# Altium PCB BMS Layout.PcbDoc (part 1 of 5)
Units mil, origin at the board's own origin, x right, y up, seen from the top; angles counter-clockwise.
Board outline 5576.78 x 4051.82 mil, 6 copper layers (Top Layer, GND1, Analog Signal, Power, GND2, Bottom Layer), stack 61.2 mil thick; 425 components, 206 nets, 1164 pads, 390 vias.
Unrouted connection lines stored in the file: 32.
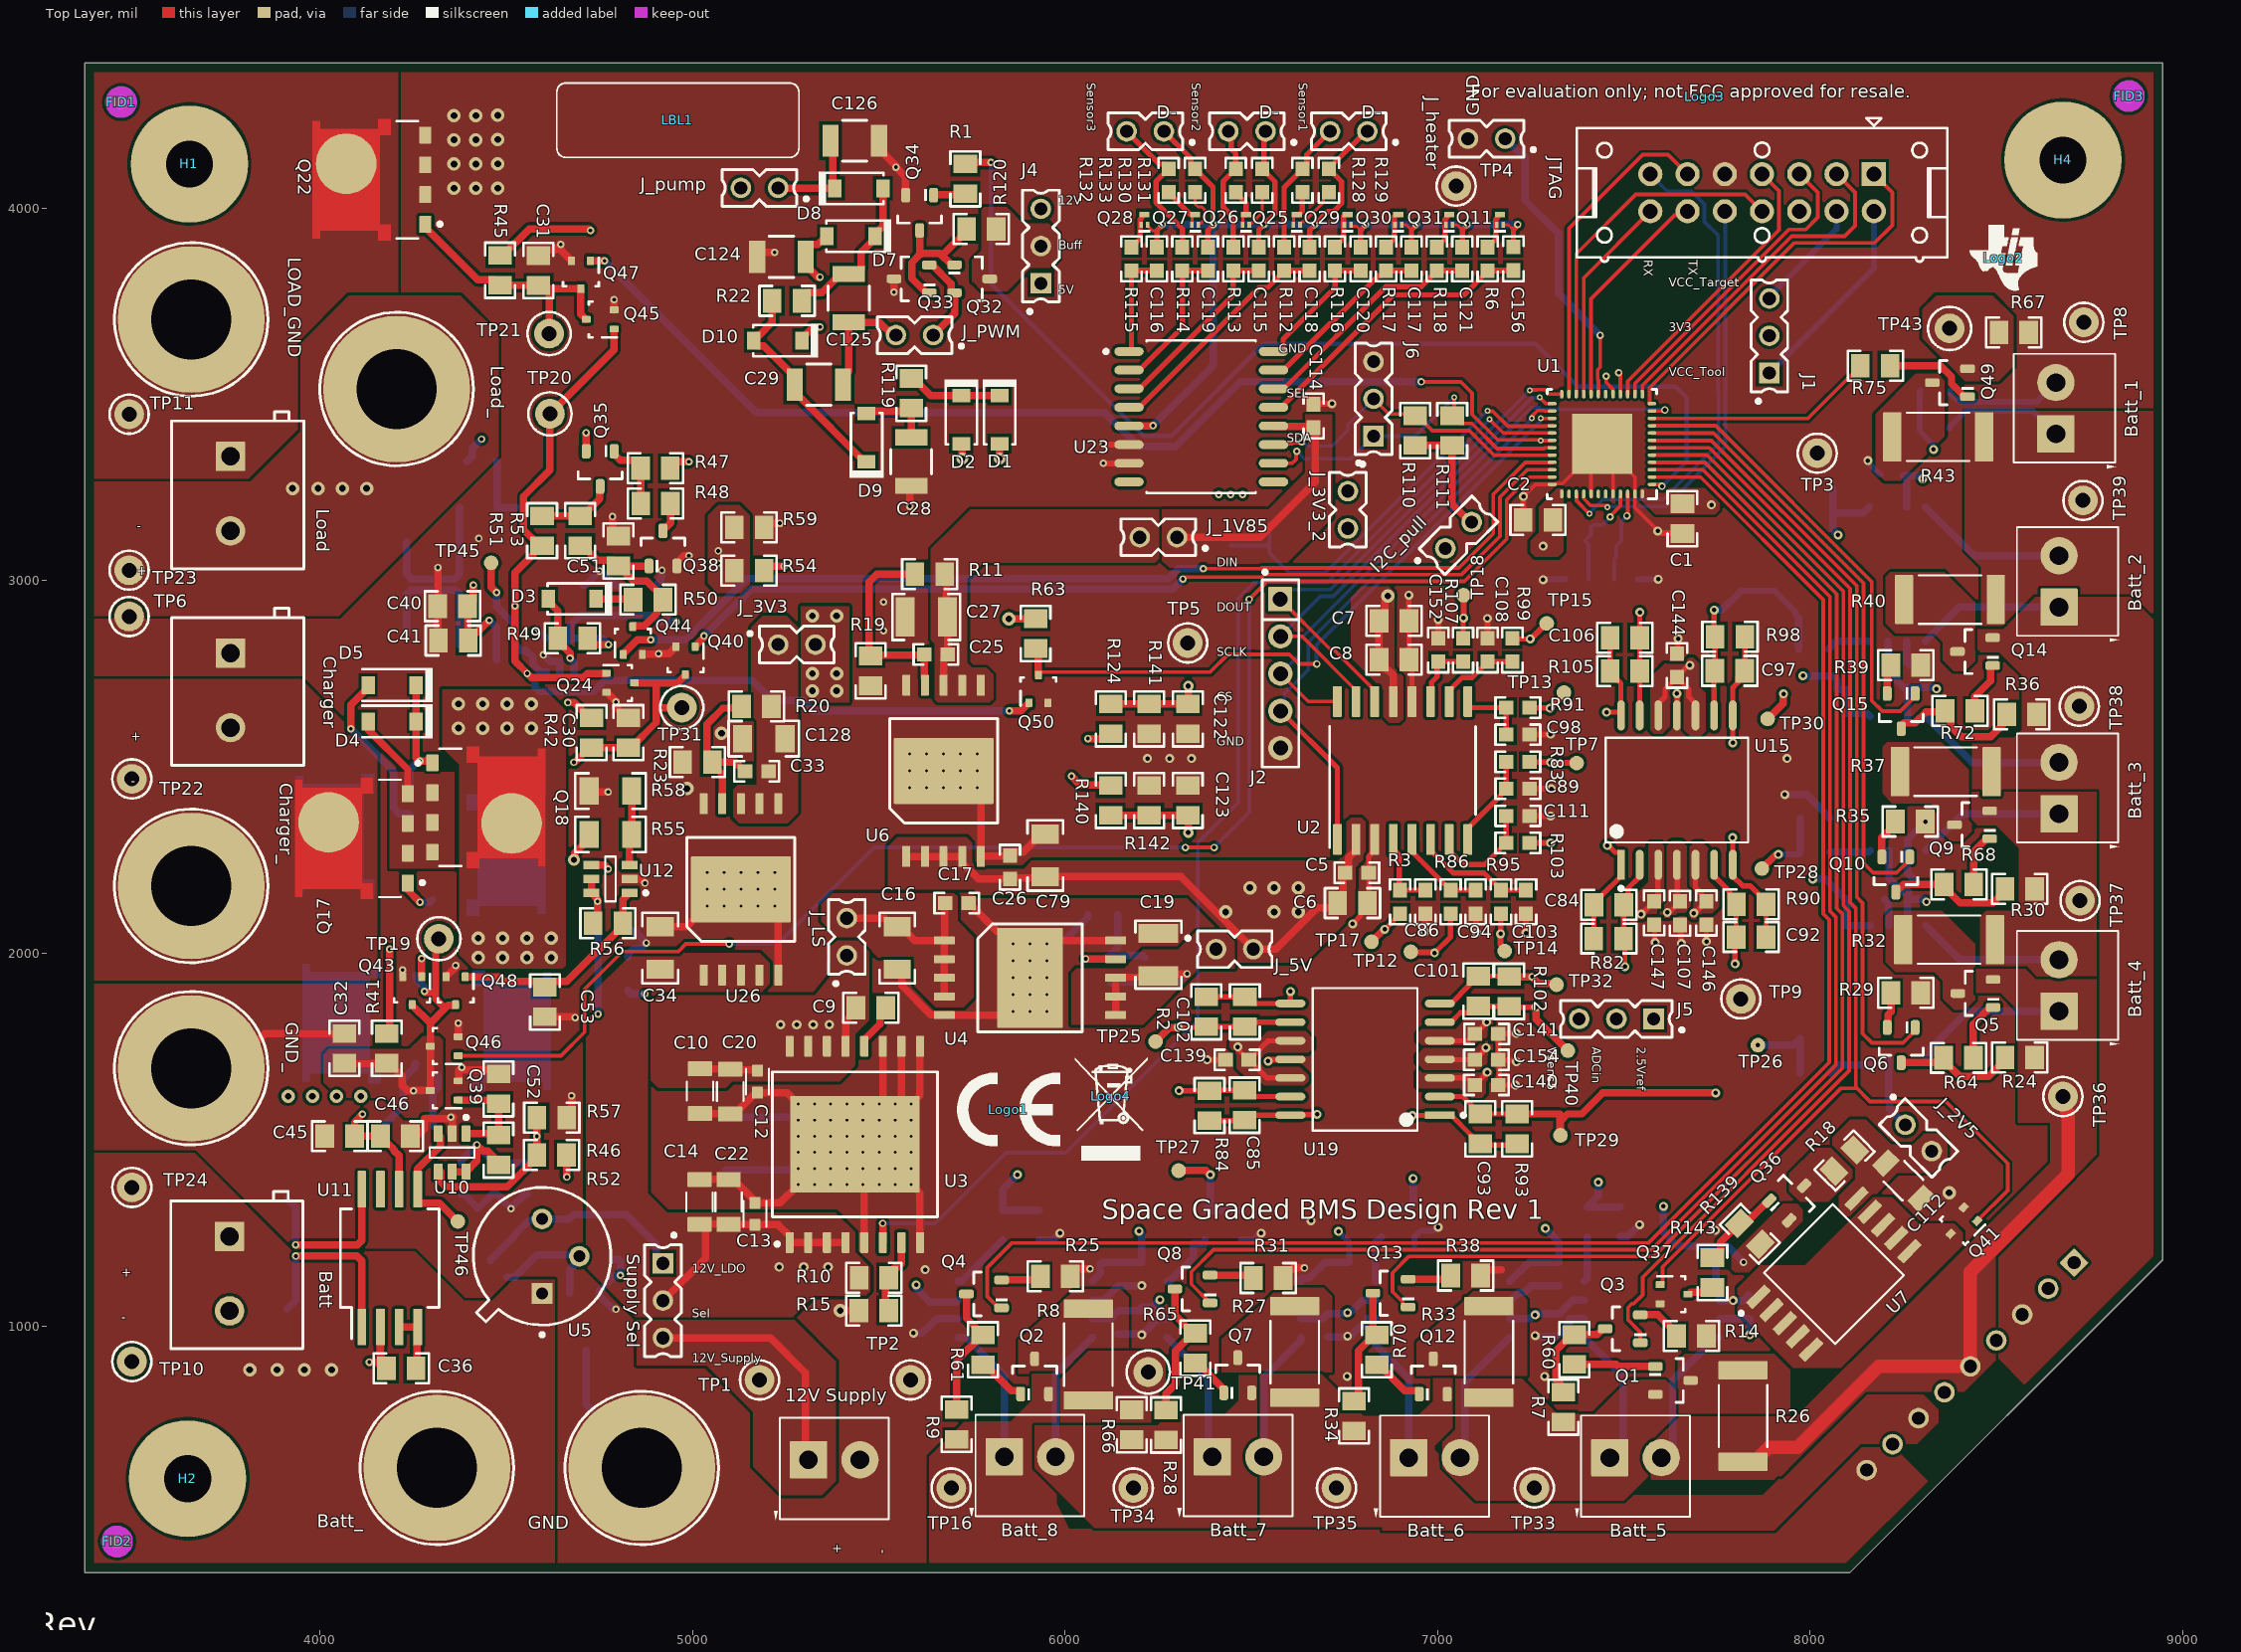
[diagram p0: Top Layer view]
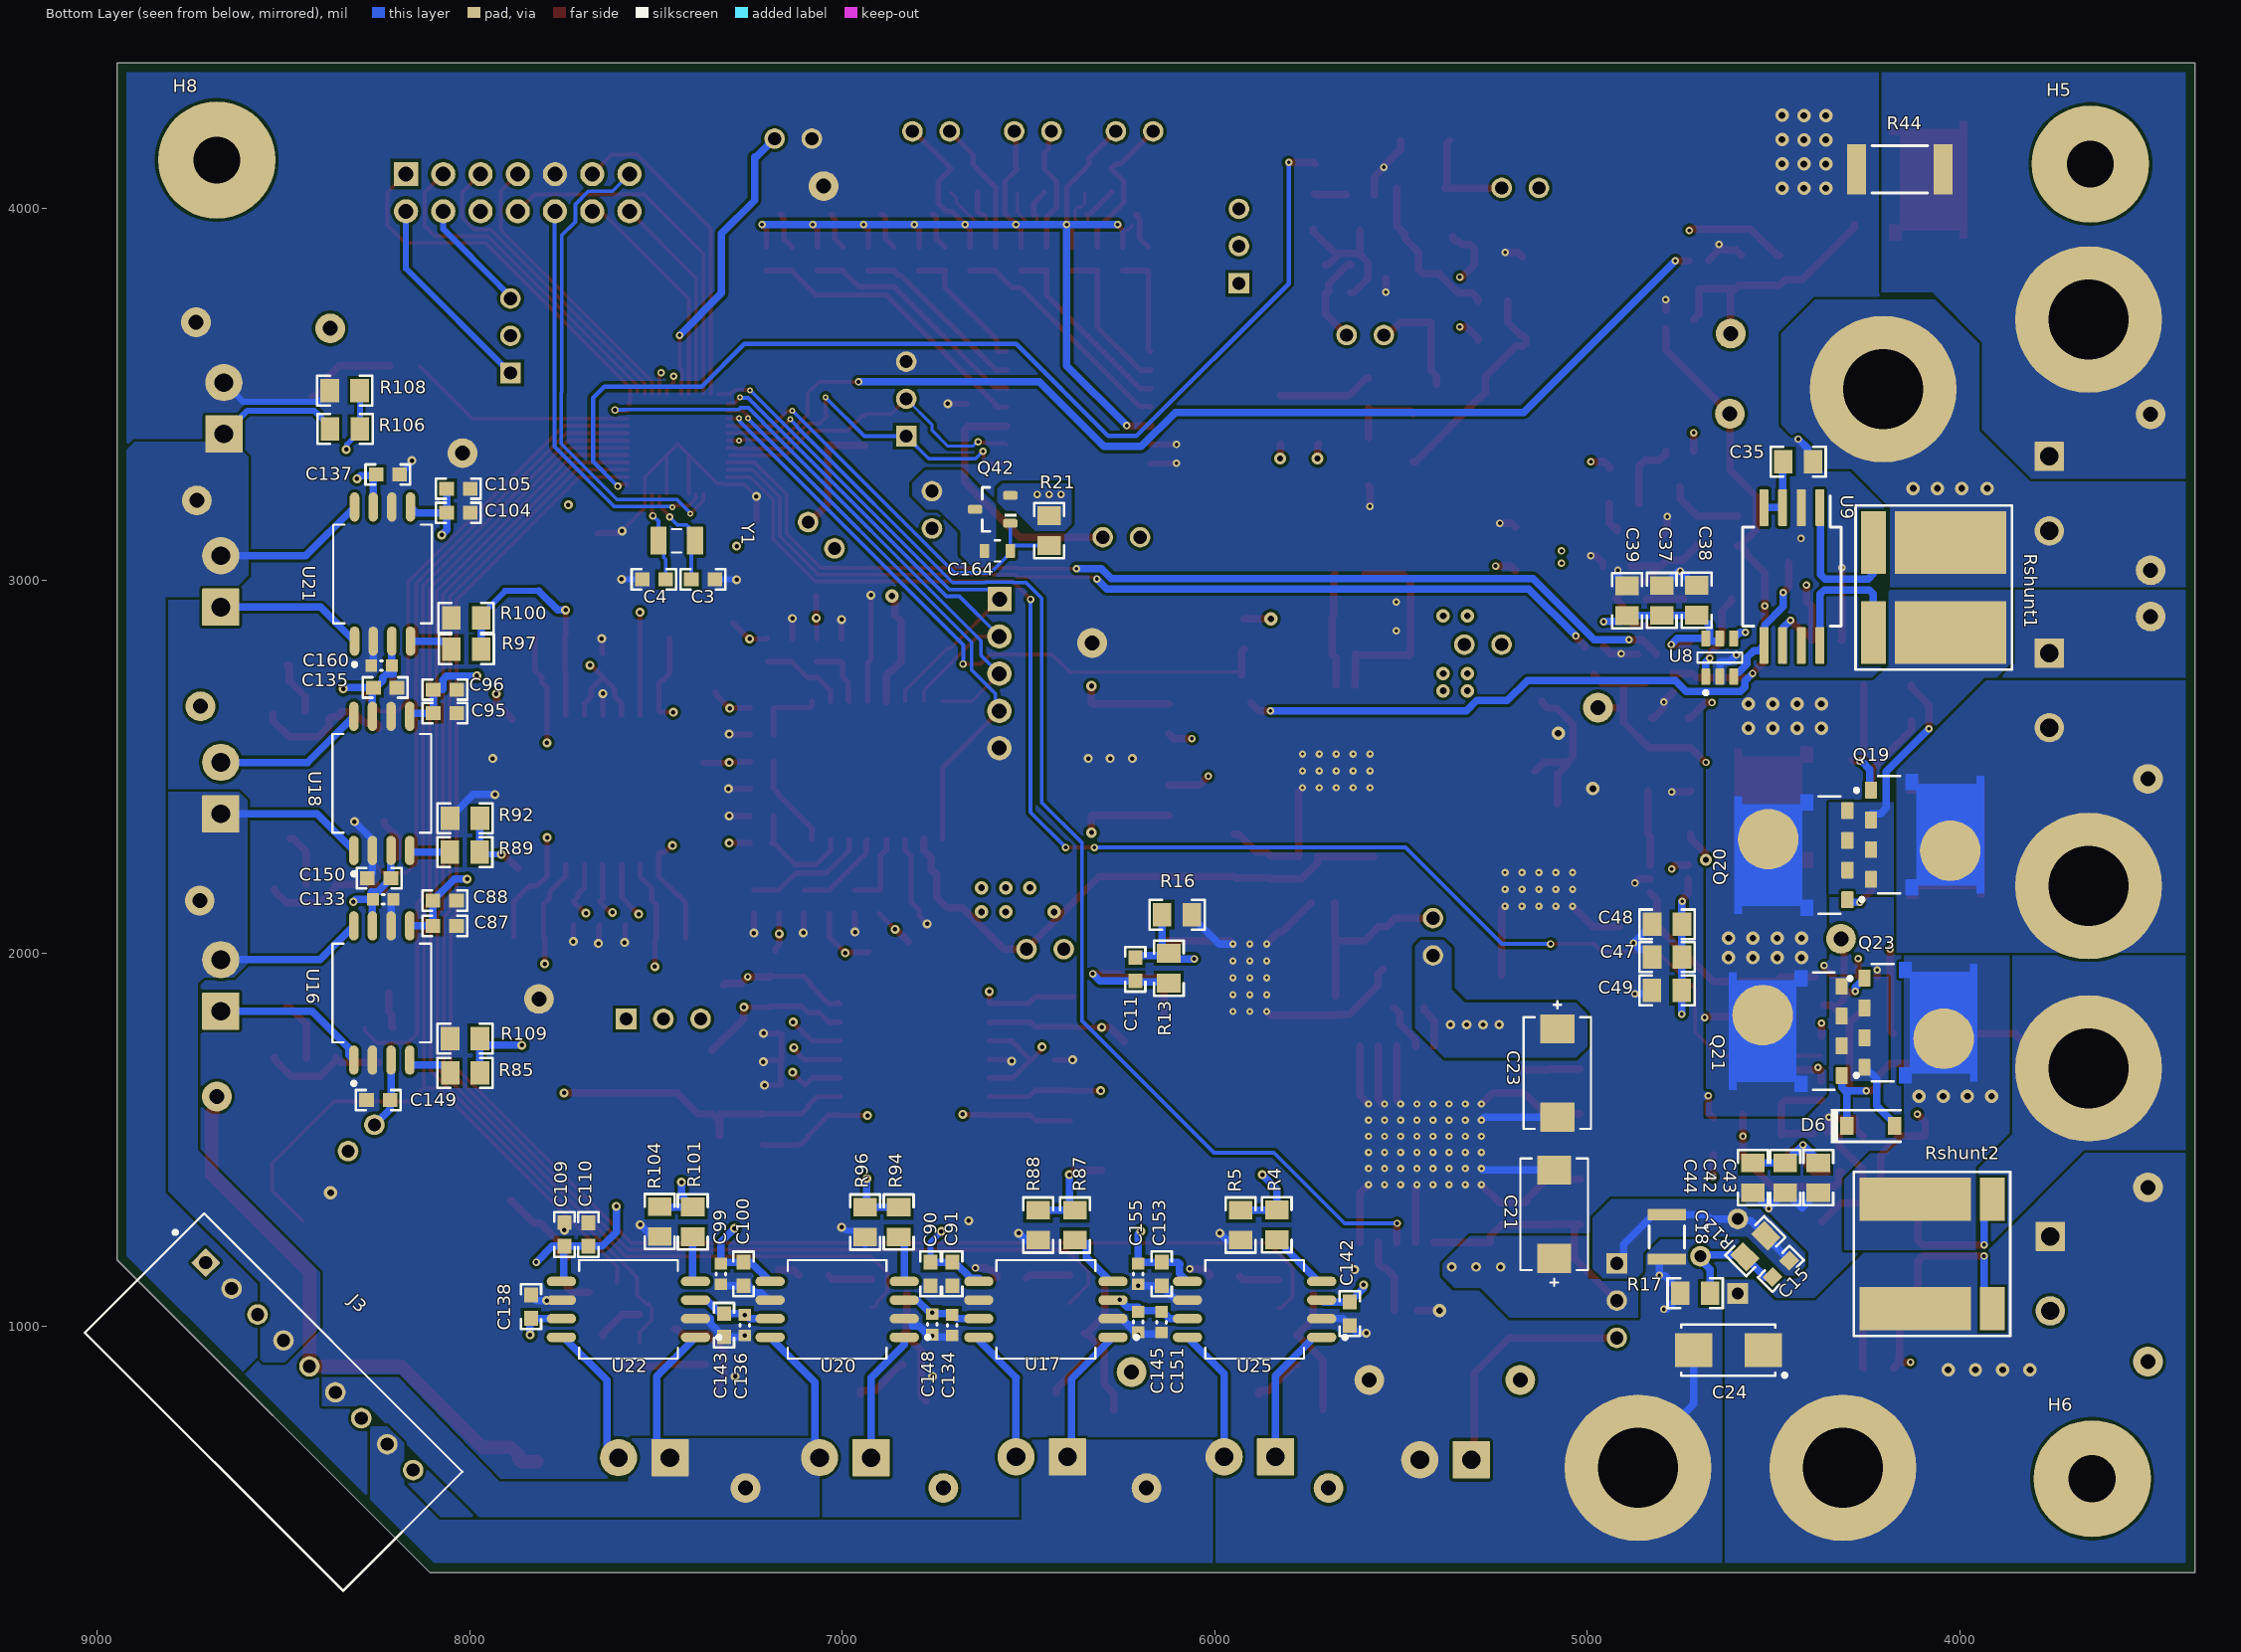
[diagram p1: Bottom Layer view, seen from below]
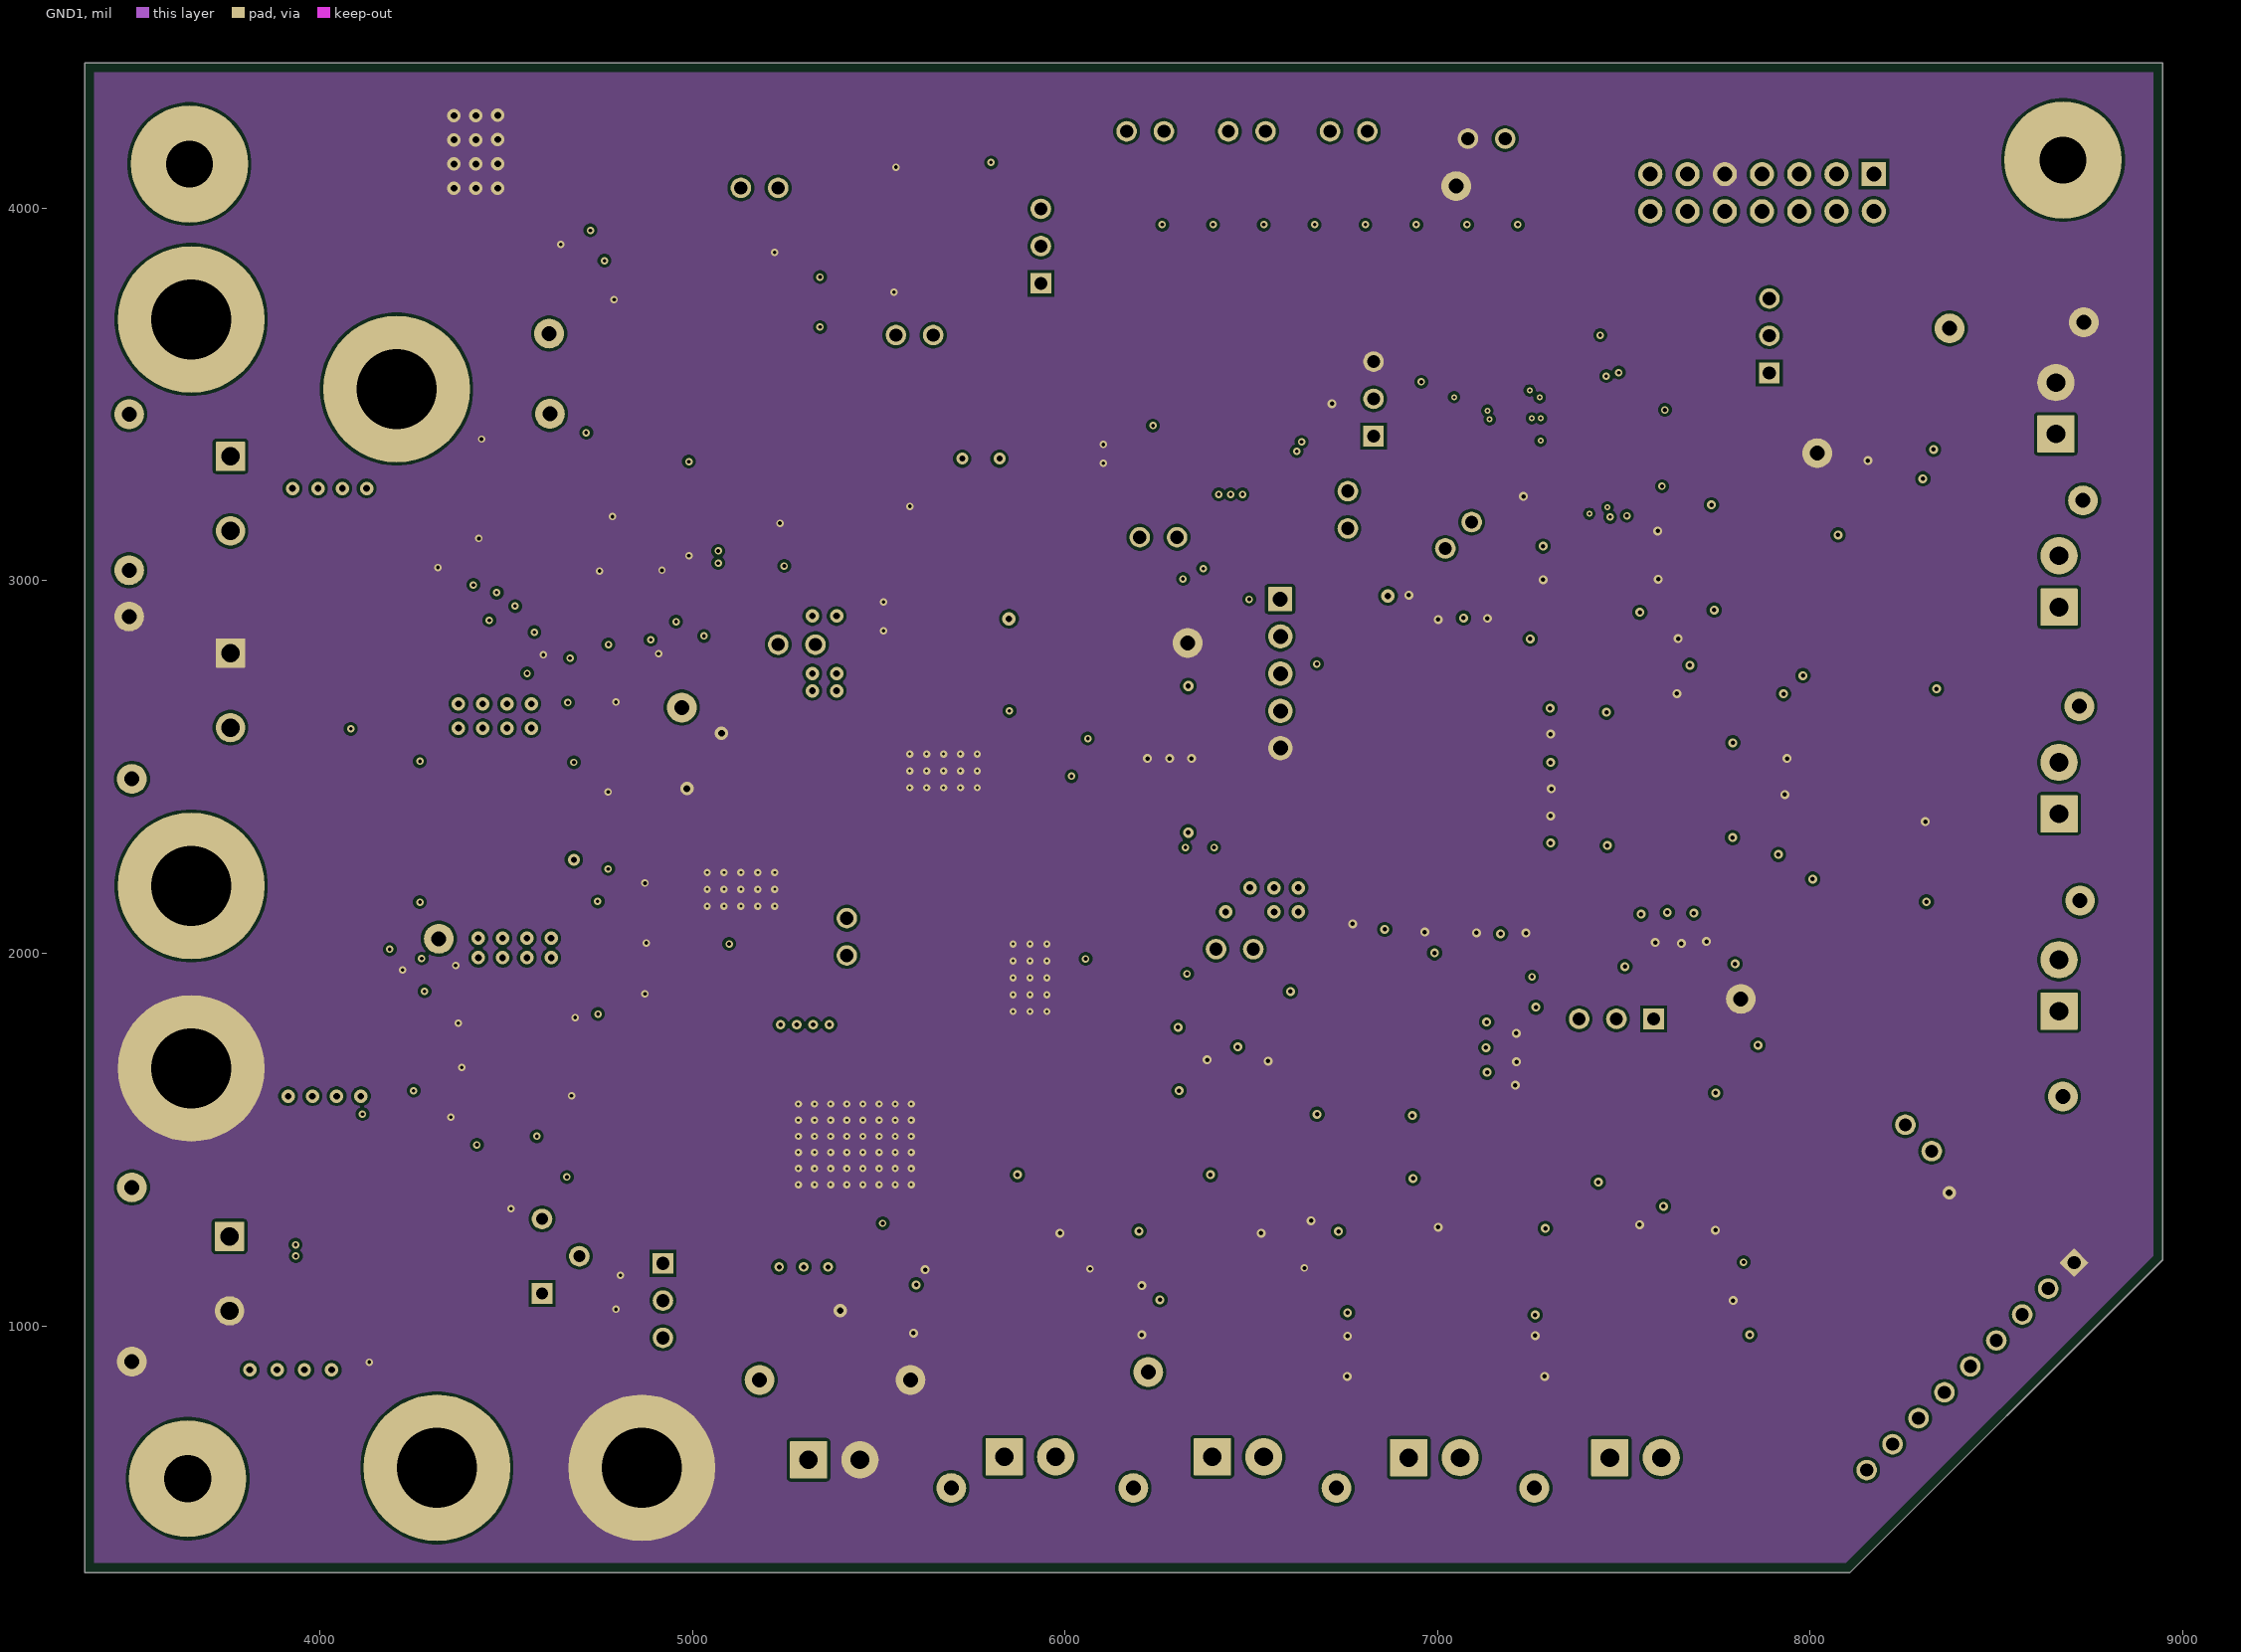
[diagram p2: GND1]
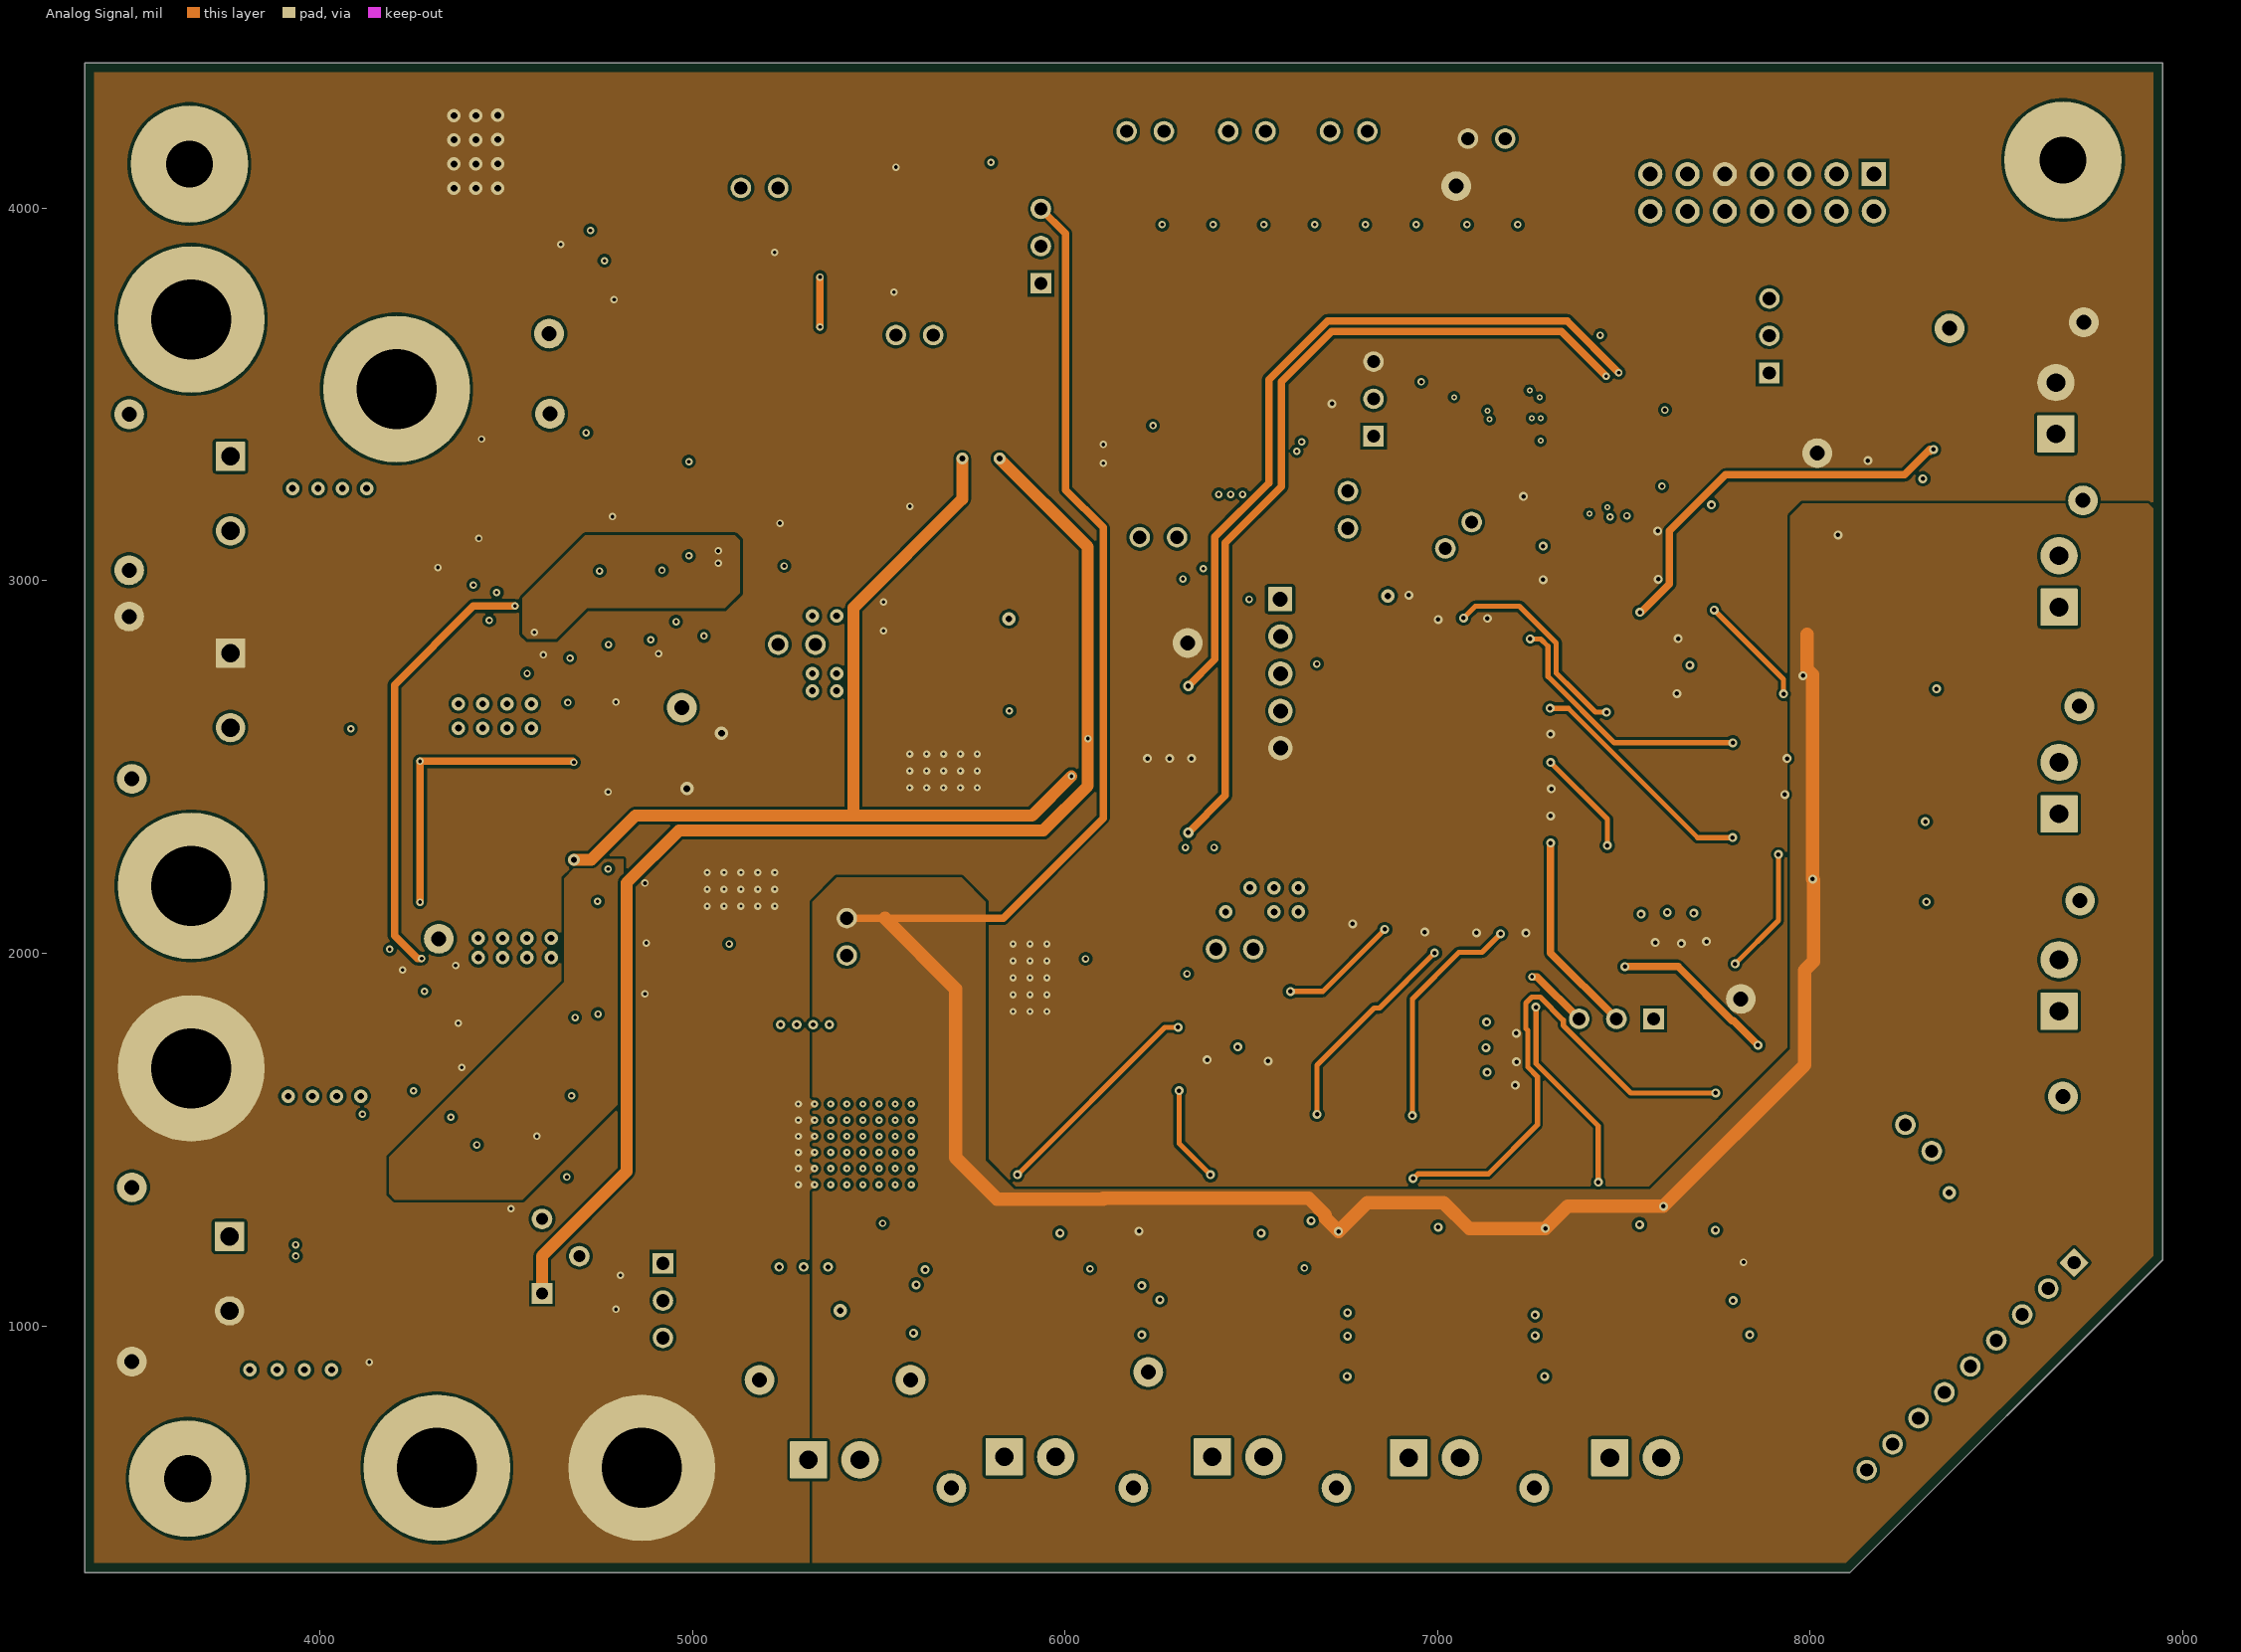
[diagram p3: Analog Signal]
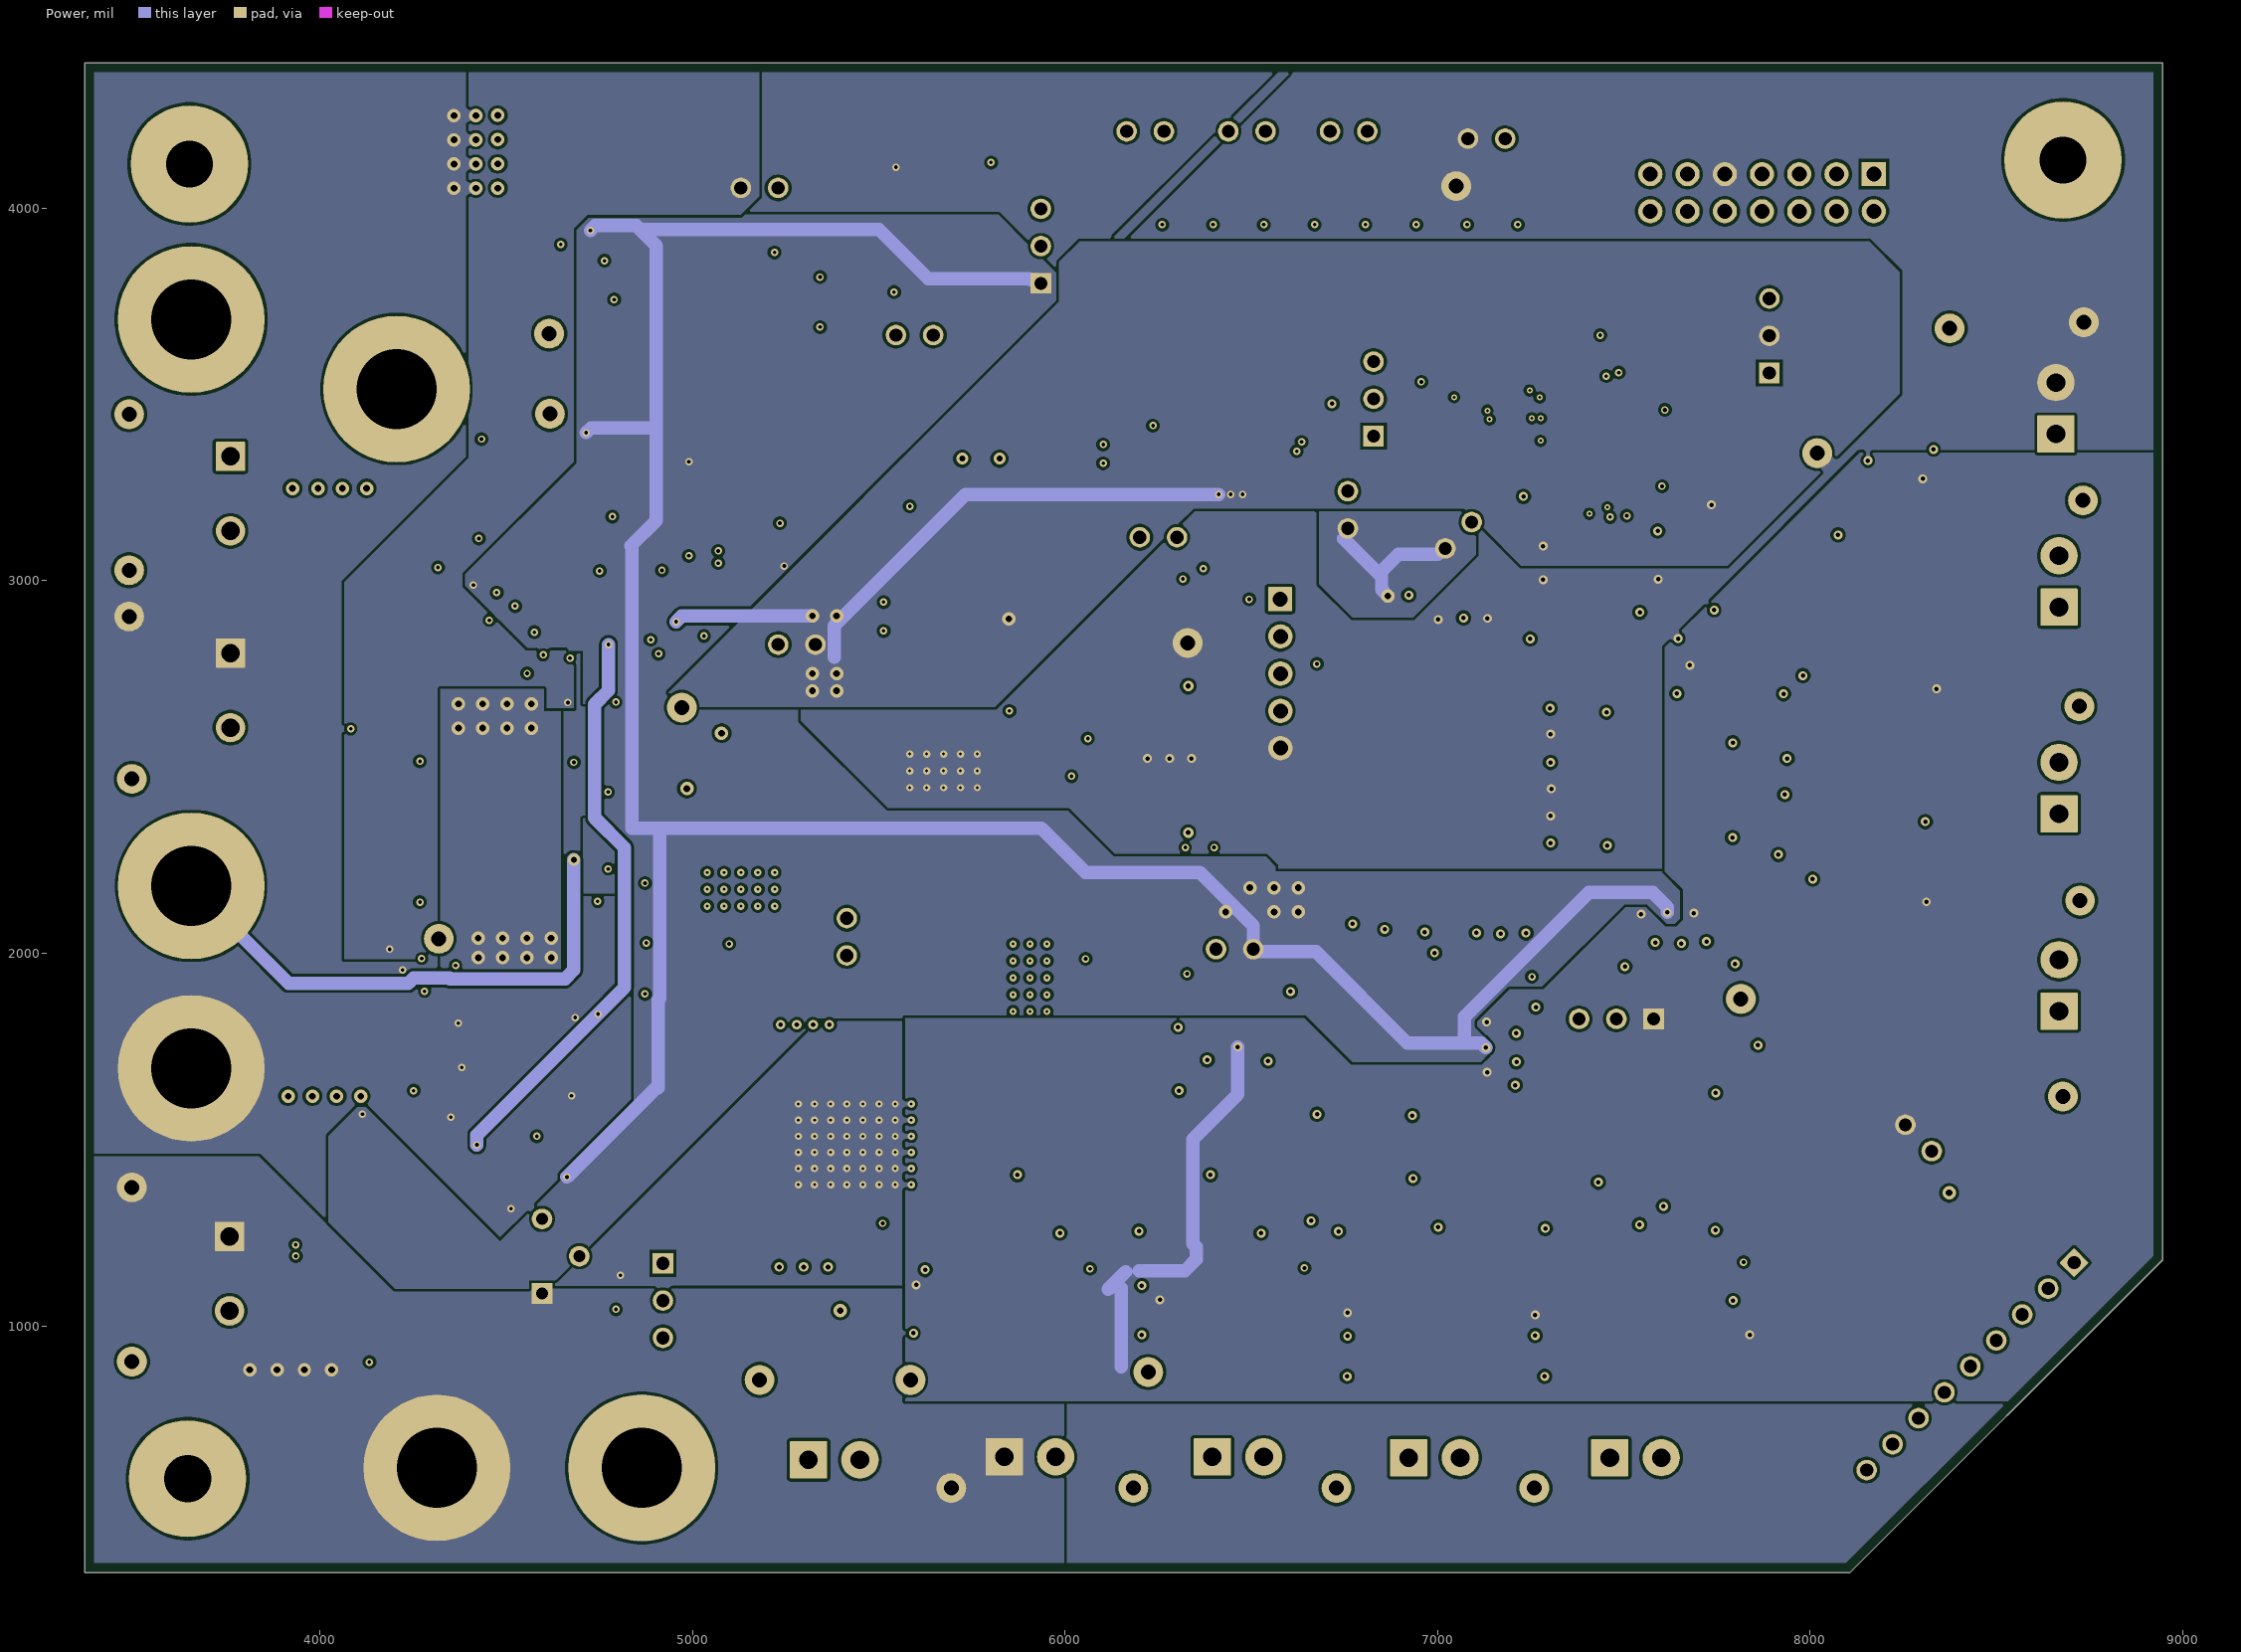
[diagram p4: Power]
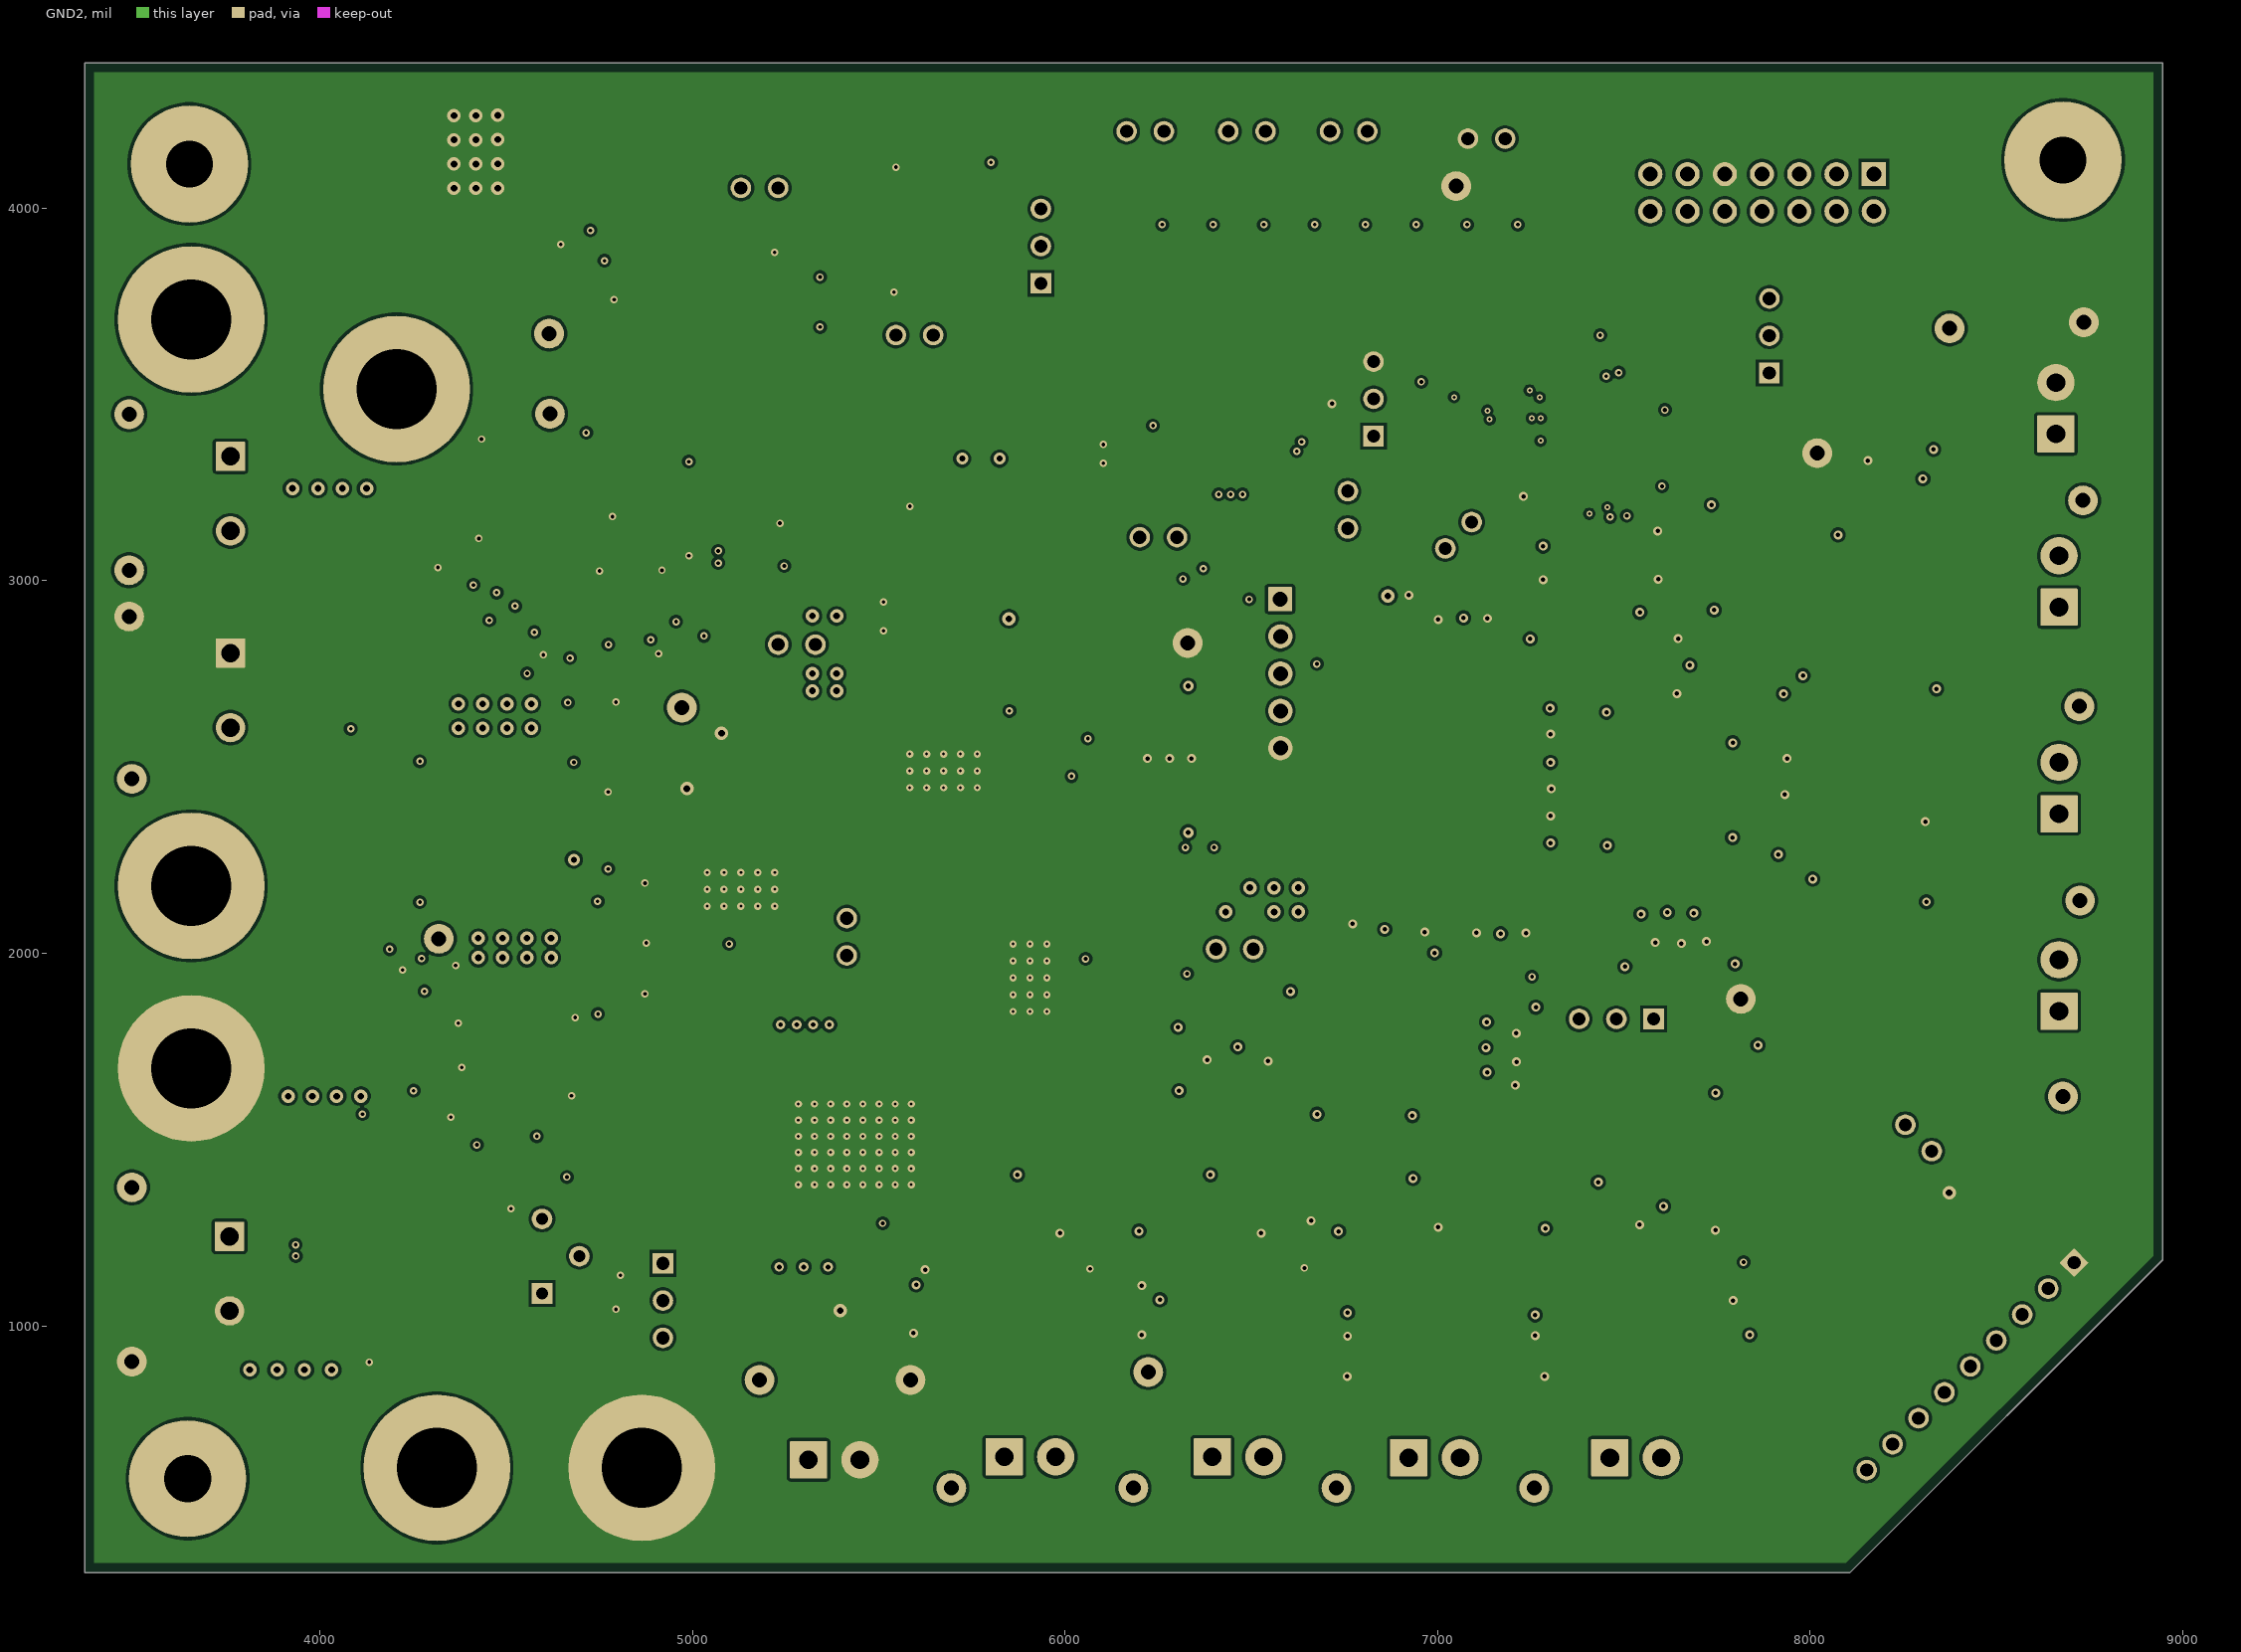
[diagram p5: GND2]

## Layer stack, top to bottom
Top Solder: solder mask 0.4, Solder Resist, Dk 3.5
Top Layer: signal copper 2.756
Dielectric 1: prepreg 2.8, PP-006, Dk 4.1
GND1: signal copper 1.378
Dielectric 3: prepreg 2.8, PP-006, Dk 4.1
Analog Signal: signal copper 1.378
Dielectric1: core 38.976, FR-4 High Tg, Dk 4.8
Power: signal copper 1.378
Dielectric 4: prepreg 2.8, PP-006, Dk 4.1
GND2: signal copper 1.378
Dielectric 2: prepreg 2.8, PP-006, Dk 4.1
Bottom Layer: signal copper 2.756
Bottom Solder: solder mask 0.4, Solder Resist, Dk 3.5

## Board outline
3369.09,337.94 3369.09,4389.76 8945.87,4389.76 8945.87,1177.18 8106.64,337.94

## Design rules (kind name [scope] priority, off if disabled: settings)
AcuteAngle [All] p1: minimum=4.50000000000000E+0001 checktracksonly=FALSE
AssemblyTestPointUsage [All] p1: valid=2
BoardOutlineClearance BoardOutlineClearance_MountingHoles [OnCopper and InComponentClass('Mounting Holes')] p1: gap=39.37 ignorepadtopadclearanceinfootprint=FALSE
BoardOutlineClearance BoardOutlineClearance_Poly [OnCopper and IsPoly] p2: gap=25 ignorepadtopadclearanceinfootprint=FALSE
BoardOutlineClearance [OnCopper and Not InComponentClass('Logo') and not InComponentClass('FiducialMark') and not InRegion(1000,500,4000,800) and not InPoly] p3: gap=75 ignorepadtopadclearanceinfootprint=FALSE except(40: Via-OutlineEdge; 50: Track-OutlineEdge Track-CavityEdge Track-CutoutEdge Track-SplitBarrior Track-SplitContinuation)
Clearance Clearance_FiducialMark [IsKeepOut and InComponentClass('FiducialMark') vs IsPad and InComponentClass('FiducialMark')] p1: gap=0 ignorepadtopadclearanceinfootprint=FALSE
Clearance [All] p2: gap=8 ignorepadtopadclearanceinfootprint=TRUE except(6: SMDPad-Via)
Clearance Clearance_Keepouts [((IsTrack Or IsArc) And Not InPoly) And IsFree and IsKeepOut vs ((IsTrack Or IsArc) And Not InPoly) And IsFree and IsKeepOut] p3: gap=0 ignorepadtopadclearanceinfootprint=FALSE
Clearance Clearance_Poly [InPolygon] p4: gap=15 ignorepadtopadclearanceinfootprint=FALSE
ComponentClearance ComponentClearance_MountingHoles_FiducialMarks [InComponentClass('Mounting Holes') vs InComponentClass('FiducialMark')] p1: gap=50 collisioncheckmode=3 verticalgap=10 showdistances=FALSE
ComponentClearance ComponentClearance_Shunt [InComponentClass('Header') vs InComponentClass('Shunt')] p2: gap=0 collisioncheckmode=3 verticalgap=0 showdistances=FALSE
ComponentClearance ComponentClearance_Logo [InComponentClass('Logo')] p3: gap=50 collisioncheckmode=3 verticalgap=10 showdistances=FALSE
ComponentClearance ComponentClearance_ScrewToNut [(HasFootprint('NY PMS 440 0025 PH')) vs (HasFootprint('Keystone_1902C'))] p4: gap=5 collisioncheckmode=3 verticalgap=10 showdistances=FALSE
ComponentClearance ComponentClearance_MountingHoles [InComponentClass('Mounting Holes')] p5: gap=39.37 collisioncheckmode=3 verticalgap=100000 showdistances=FALSE
ComponentClearance ComponentClearance_SmallPassives [HasFootprint('0201*') or HasFootprint('0402*') or HasFootprint('0508') or HasFootprint('0603*') or HasFootprint('0612') or HasFootprint('0805*') or HasFootprint('0815*') or HasFootprint('0830*') or HasFootprint('1206*') or HasFootprint('1210*') or HasFootprint('1808*') or HasFootprint('1812*') or HasFootprint('1825*') or HasFootprint('2010*') or HasFootprint('2220*') or HasFootprint('2225*') or HasFootprint('2512*') or HasFootprint('2728*') or HasFootprint('3518*') vs HasFootprint('0201*') or HasFootprint('0402*') or HasFootprint('0508') or HasFootprint('0603*') or HasFootprint('0612') or HasFootprint('0805*') or HasFootprint('0815*') or HasFootprint('0830*') or HasFootprint('1206*') or HasFootprint('1210*') or HasFootprint('1808*') or HasFootprint('1812*') or HasFootprint('1825*') or HasFootprint('2010*') or HasFootprint('2220*') or HasFootprint('2225*') or HasFootprint('2512*') or HasFootprint('2728*') or HasFootprint('3518*')] p6: gap=14.96 collisioncheckmode=3 verticalgap=10 showdistances=FALSE
ComponentClearance ComponentClearance_THtoSMT [IsThruComponent vs IsSMTComponent] p7: gap=9.84 collisioncheckmode=3 verticalgap=30 showdistances=FALSE
ComponentClearance ComponentClearance_THtoTH [IsThruComponent vs IsThruComponent] p8: gap=9.84 collisioncheckmode=3 verticalgap=30 showdistances=FALSE
ComponentClearance [All] p9: gap=9.84 collisioncheckmode=3 verticalgap=10 showdistances=FALSE
DiffPairsRouting [All] p1: maxlimit=100 minlimit=10 mostfreqgap=10 toplayer_minwidth=15 toplayer_maxwidth=15 toplayer_prefwidth=15 midlayer1_minwidth=15 midlayer1_maxwidth=15 midlayer1_prefwidth=15 midlayer2_minwidth=15 midlayer2_maxwidth=15 midlayer2_prefwidth=15 midlayer3_minwidth=15 midlayer3_maxwidth=15 midlayer3_prefwidth=15 midlayer4_minwidth=15 midlayer4_maxwidth=15 midlayer4_prefwidth=15 bottomlayer_minwidth=15 bottomlayer_maxwidth=15 bottomlayer_prefwidth=15 maxuncoupledlength=1000
FabricationTestPointUsage TestPointUsage [All] p1: valid=2 allowmultiple=FALSE
FabricationTestpoint Testpoint [All] p1: side=3 testpointundercomponent=TRUE minsize=40 maxsize=100 preferedsize=60 minholesize=0 maxholesize=40 preferedholesize=32 testpointgrid=1 allowsidetop=TRUE allowsidebottom=TRUE usegrid=TRUE gridtolerance=0.01
FanoutControl Fanout_LCC [IsLCC] p1: bgadir=Out bgaviamode=Centered fanoutstyle=Auto fanoutdirection=Alternating viagrid=1 // Fanout_LCC (Default Rule)
FanoutControl Fanout_BGA [IsBGA] p2: bgadir=Out bgaviamode=Centered fanoutstyle=Auto fanoutdirection=Alternating viagrid=1 // Fanout_BGA (Default Rule)
FanoutControl Fanout_Default [All] p4: bgadir=Out bgaviamode=Centered fanoutstyle=Auto fanoutdirection=Alternating viagrid=1 // Fanout_Default (Default Rule)
FanoutControl Fanout_Small [(CompPinCount < 5)] p5: bgadir=Out bgaviamode=Centered fanoutstyle=Auto fanoutdirection=OutThenIn viagrid=1 // Fanout_Small (Default Rule)
HoleSize [All] p1: absolutevalues=TRUE maxlimit=251 minlimit=7.87 maxpercent=80.000 minpercent=20.000
MinimumAnnularRing MinimumAnnularRing_ThermalPadVias [IsVia and InAnyComponent] p1: minimumring=5.91
MinimumAnnularRing [All] p2: minimumring=4
MinimumSolderMaskSliver MinimumSolderMaskSliver_Logo [InComponentClass('Logo') vs InComponentClass('Logo')] p1: minsoldermaskwidth=0.7
MinimumSolderMaskSliver [All] p2: minsoldermaskwidth=3
NetAntennae [All] p1 off: netantennaetolerance=0
PlaneConnect [All] p1: planeconnectstyle=Direct reliefexpansion=10 reliefentries=4 reliefconductorwidth=10 reliefairgap=10
PolygonConnect [All] p1: connectstyle=Direct reliefconductorwidth=10 reliefentries=4 polygonreliefangle="90 Angle" airgapwidth=10
RoutingVias ThermalPadVias [IsVia and InAnyComponent] p1: holewidth=7.87 width=19.68 viastyle="Through Hole" minholewidth=6 minwidth=16 maxholewidth=12.99 maxwidth=23.62
RoutingVias [All] p2: holewidth=10 width=20 viastyle="Through Hole" minholewidth=8 minwidth=16 maxholewidth=40 maxwidth=65
SilkToBoardRegionClearance [Not ((IsComment or IsDesignator) And (Hide <> 'False')) and not InRegion(1000,500,4000,800)] p1:
SilkToSilkClearance SilkToSilkClearance_Pb-FreeLogo [(HasFootprint('Pb-Free_Overlay_Medium') OR HasFootprint('Pb-Free_Overlay_Small')) vs (HasFootprint('Pb-Free_Overlay_Medium') OR HasFootprint('Pb-Free_Overlay_Small'))] p1: silktosilkclearance=0
SilkToSilkClearance [All] p2: silktosilkclearance=1
SilkToSolderMaskClearance SilkToComponentPadClearance [(IsPad or IsFill or IsRegion) and InAnycomponent] p1: minsilkscreentomaskgap=0 clearancetoexposedcopper=TRUE
SilkToSolderMaskClearance "Silk to Solder Mask Opening" [All] p2: minsilkscreentomaskgap=3 clearancetoexposedcopper=FALSE
SolderMaskExpansion [All] p1: expansion=1.97 istentingtop=FALSE
UnRoutedNet [All] p1: checkbadconnections=TRUE
Width [All] p1: maxlimit=100 minlimit=6 preferedwidth=20 midlayer1_prefwidth=10 midlayer2_prefwidth=10 midlayer4_prefwidth=36 minimp=50.000000 maximp=50.000000 favimp=50.000000 checkconnectedcopper=TRUE
13 further rules are at their usual default settings.

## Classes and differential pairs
component class "Batt_Stack_Control (NMOS)": Batt Batt_ C28 C29 C30 C31 C32 C35 C36 C37 C38 C39 C40 C41 C42 C43 C44 C45 C46 C47 C48 C49 C51 C52 C53 C124 C125 C126 Charger Charger_ D1 D2 D3 D4 D5 D6 D7 D8 D9 D10 GND GND_ J4 J_pump J_PWM Load Load_ LOAD_GND Q17 Q18 Q19 Q20 Q21 Q22 Q23 Q24 Q32 Q33 Q34 Q35 Q38 Q39 Q40 Q43 Q44 Q45 Q46 Q47 Q48 Q50 Q100 R1 R22 R41 R42 R44 R45 R46 R47 R48 R49 R50 R51 R52 R53 R54 R55 R56 R57 R58 R59 R63 R119 R120 Rshunt1 Rshunt2 TP11 TP19 TP20 TP21 TP22 TP23 TP24 TP31 TP45 TP46 U8 U9 U10 U11 U12
component class Balancer: Batt_1 Batt_2 Batt_3 Batt_4 Batt_5 Batt_6 Batt_7 Batt_8 J3 Q1 Q2 Q3 Q4 Q5 Q6 Q7 Q8 Q9 Q10 Q12 Q13 Q14 Q15 Q49 R7 R8 R9 R14 R24 R25 R26 R27 R28 R29 R30 R31 R32 R33 R34 R35 R36 R37 R38 R39 R40 R43 R60 R61 R64 R65 R66 R67 R68 R70 R72 R75 TP16 TP33 TP34 TP35 TP36 TP37 TP38 TP39 TP41 TP43
component class "Temp Sensing": C114 C115 C116 C117 C118 C119 C120 C121 C156 I2C_pull Q11 Q25 Q26 Q27 Q28 Q29 Q30 Q31 R6 R110 R111 R112 R113 R114 R115 R116 R117 R118 R128 R129 R130 R131 R132 R133 Sensor1 Sensor2 Sensor3 U23
component class PCB_Project_Hardware: !PCB FID1 FID2 FID3 H1 H2 H4 H5 H6 H8 LBL1 Logo1 Logo2 Logo3 Logo4
component class Monitor: C84 C85 C86 C87 C88 C89 C90 C91 C92 C93 C94 C95 C96 C97 C98 C99 C100 C101 C102 C103 C104 C105 C106 C107 C108 C109 C110 C133 C134 C135 C136 C137 C138 C151 C152 C153 C154 C155 R2 R3 R4 R5 R82 R83 R84 R85 R86 R87 R88 R89 R90 R91 R92 R93 R94 R95 R96 R97 R98 R99 R100 R101 R102 R104 R105 R106 R107 R108 R109 TP7 TP12 TP13 TP14 TP15 TP17 TP18 TP25 TP26 TP27 TP28 TP29 TP30 TP32 TP40 U15 U16 U17 U18 U19 U20 U21 U22 U25
component class MCU_ADC: C1 C2 C3 C4 C5 C6 C7 C8 C111 C122 C123 J1 J2 J5 J6 J_heater JTAG R103 R124 R140 R141 R142 U1 U2 Y1
component class Header: I2C_pull J1 J2 J4 J5 J6 J_1V85 J_2V5 J_3V3 J_3V3_2 J_5V J_heater J_LS J_pump J_PWM Sensor1 Sensor2 Sensor3 "Supply Sel"
component class "Power Tree": "12V Supply" C9 C10 C11 C12 C13 C14 C15 C16 C17 C18 C19 C20 C21 C22 C23 C24 C25 C26 C27 C33 C34 C79 C112 C128 C139 C140 C141 C142 C143 C144 C145 C146 C147 C148 C149 C150 C160 C164 J_1V85 J_2V5 J_3V3 J_3V3_2 J_5V J_LS Q36 Q37 Q41 Q42 R10 R11 R12 R13 R15 R16 R17 R18 R19 R20 R21 R23 R139 R143 "Supply Sel" TP1 TP2 TP3 TP4 TP5 TP6 TP8 TP9 TP10 U3 U4 U5 U6 U7 U26
component class "Mounting Holes": H1 H2 H4
component class Logo: Logo2
component class FiducialMark: FID1 FID2 FID3
component class Label: LBL1

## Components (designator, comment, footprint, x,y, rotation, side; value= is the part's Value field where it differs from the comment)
"12V Supply" "ED555/2DS" TERM_BLK_ED555-2DS 5311.39,640.35 r0 top
Batt "ED120/2DS" On-Shore_ED120_2DS 3757.4,1140.16 r270 top
Batt_ "575-8" Keystone575-8 4313.98,618.56 r90 top
Batt_1 "ED555/2DS" TERM_BLK_ED555-2DS 8659.37,3393.9 r90 top
Batt_2 "ED555/2DS" TERM_BLK_ED555-2DS 8667.67,2929.11 r90 top
Batt_3 "ED555/2DS" TERM_BLK_ED555-2DS 8667.67,2374.46 r90 top
Batt_4 "ED555/2DS" TERM_BLK_ED555-2DS 8667.67,1844.64 r90 top
Batt_5 "ED555/2DS" TERM_BLK_ED555-2DS 7462.08,646.06 r0 top
Batt_6 "ED555/2DS" TERM_BLK_ED555-2DS 6922.45,646.06 r0 top
Batt_7 "ED555/2DS" TERM_BLK_ED555-2DS 6395.17,648.22 r0 top
Batt_8 "ED555/2DS" TERM_BLK_ED555-2DS 5836.73,648.22 r0 top
C1 "C0805C105K8RACTU" 0805_HV 7656.96,3166.58 r270 top value=1uF
C2 "ECPU1C104MA5" 0805_HV 7269.11,3163.03 r180 top value=0.1uF
C3 "C0603C100J5GACTU" 0603 7373.04,3003.42 r180 bottom value=10pF
C4 "C0603C100J5GACTU" 0603 7505.03,3003.42 r0 bottom value=10pF
C5 "CGA3E1X7R1C105K080AC" 0603 6782.98,2216.45 r0 top value=1uF
C6 "ECPU1C104MA5" 0805_HV 6771.41,2134.77 r0 top value=0.1uF
C7 "C0805C105K8RACTU" 0805_HV 6882.73,2891.81 r0 top value=1uF
C8 "ECPU1C104MA5" 0805_HV 6882.73,2788.32 r0 top value=0.1uF
C9 "08055A102FAT2A" 0805_HV 5478.48,1853.49 r0 top value=1000pF
C10 "GMC31X7R106K50NT" FP-GMC31X7R106K50NT_1206-MFG 5019.89,1629.95 r90 top value=10µF
C11 "C0603C104K5RACTU" 0603 6213.39,1957.01 r90 bottom value=0.1uF
C12 "06035C104J4Z2A" FP-06035C104J4Z2A_0603-MFG 5174.34,1655.41 r90 top value=100nF
C13 "06035C104J4Z2A" FP-06035C104J4Z2A_0603-MFG 5167.48,1300.68 r270 top value=100nF
C14 "GMC31X7R106K50NT" FP-GMC31X7R106K50NT_1206-MFG 5018.97,1332.65 r270 top value=10µF
C15 "C0603C104K5RACTU" 0603 4480.34,1152.99 r315 bottom value=0.1uF
C16 "GRM31CR71E106MA12L" 1206 5549.31,2014.09 r270 top value=10uF
C17 "C0603C104K5RACTU" 0603 5709.38,2134.77 r0 top value=0.1uF
C18 "1uF" CAPC3225X270X30LL30 4786.35,1238.48 r90 bottom
C19 "GRM32DR71E106KA12L" 1210_220 6250.36,1996.43 r90 top value=10uF
C20 "GMC31X7R106K50NT" FP-GMC31X7R106K50NT_1206-MFG 5101.11,1628.89 r90 top value=10µF
C21 "T521D157M020ATE050" FP-T521D157M020ATE050_2917-MFG 5088.88,1299.48 r90 bottom value=150µF
C22 "GMC31X7R106K50NT" FP-GMC31X7R106K50NT_1206-MFG 5096.89,1332.65 r270 top value=10µF
C23 "T521D157M020ATE050" FP-T521D157M020ATE050_2917-MFG 5080.44,1678.65 r270 bottom value=150µF
C24 "293D105X9050C2TE3" 6032-28 4621.36,934.53 r0 bottom value=1uF
C25 "C0603C104K5RACTU" 0603 5653.39,2802.2 r180 top value=0.1uF
C26 "C0603C104K5RACTU" 0603 5851.84,2230.79 r90 top value=0.1uF
C27 "GRM32DR71E106KA12L" 1210_220 5627.53,2902.69 r180 top value=10uF
C28 "CGA6P3X7S1H106K250AB" 1210_280 5586.93,3319.65 r270 top value=10uF
C29 "CGA6P3X7S1H106K250AB" 1210_280 5339.24,3526.19 r0 top value=10uF
C30 "08055C104KAT2A" 0805_HV 4828.24,2592.04 r90 top value=0.1uF
C31 "08055C104KAT2A" 0805_HV 4586.61,3832.79 r90 top value=0.1uF
C32 "08055C104KAT2A" 0805_HV 4065.85,1744.68 r90 top value=0.1uF
C33 "C0603C104K5RACTU" 0603 5172.66,2488.45 r180 top value=0.1uF
C34 "GRM31CR71E106MA12L" 1206 4913.37,2014.09 r90 top value=10uF
C35 "CC0805CRNP09BN1R0" 0805_HV 4434.01,3319.65 r180 bottom value=1pF
C36 "CC0805CRNP09BN1R0" 0805_HV 4218.22,885.77 r180 top value=1pF
C37 "GCM21BR71H104KA37K" 0805_HV 4800.4,2947.13 r90 bottom value=0.1uF
C38 "C0805C101J1RACTU" 0805_HV 4706.31,2947.74 r90 bottom value=100pF
C39 "GCJ21BR71H105MA01L" 0805_HV 4893.6,2946.24 r90 bottom value=1uF
C40 "GCM21BR71H104KA37K" 0805_HV 4356.14,2931.53 r180 top value=0.1uF
C41 "QMK212B7103KG-T" 0805_HV 4357.87,2839.61 r180 top value=0.01uF
C42 "GCM21BR71H104KA37K" 0805_HV 4468.55,1397.48 r270 bottom value=0.1uF
C43 "C0805C101J1RACTU" 0805_HV 4379.97,1397.48 r270 bottom value=100pF
C44 "GCJ21BR71H105MA01L" 0805_HV 4555.99,1397.48 r270 bottom value=1uF
C45 "GCM21BR71H104KA37K" 0805_HV 4053.07,1508.85 r180 top value=0.1uF
C46 "QMK212B7103KG-T" 0805_HV 4202.54,1508.85 r0 top value=0.01uF
C47 "GCM21BR71H104KA37K" 0805_HV 4786.09,1989.7 r0 bottom value=0.1uF
C48 "C0805C101J1RACTU" 0805_HV 4786.09,2077.52 r0 bottom value=100pF
C49 "GCJ21BR71H105MA01L" 0805_HV 4786.27,1900.51 r0 bottom value=1uF
C51 "08055A501GAT2A" 0805_HV 4801.43,3079.87 r90 top value=500pF
C52 "08055A501GAT2A" 0805_HV 4478.99,1635.98 r90 top value=500pF
C53 "QMK212B7103KG-T" 0805_HV 4604.15,1869.4 r270 top value=0.01uF
C79 "GRM31CR71E106MA12L" 1206 5946.62,2262.57 r90 top value=10uF
C84 "GRM21BR71C105KA01L" 0805_HV 7459.45,2130.24 r0 top value=1uF
C85 "GRM21BR71C105KA01L" 0805_HV 6481.86,1592.05 r90 top value=1uF
C86 "06035A681FAT2A" 0603 6966.99,2137.8 r270 top value=680pF
C87 "CGA3E2X7R1H104K080AA" 0603 8066.42,2073.3 r0 bottom value=0.1uF
C88 "C1608X5R1E105K080AC" 0603 8066.42,2141.33 r0 bottom value=1uF
C89 "06035A681FAT2A" 0603 7215.31,2441.46 r0 top value=680pF
C90 "CGA3E2X7R1H104K080AA" 0603 6762.5,1139.35 r90 bottom value=0.1uF
C91 "C1608X5R1E105K080AC" 0603 6704.63,1139.35 r90 bottom value=1uF
C92 "GRM21BR71C105KA01L" 0805_HV 7841.24,2043.81 r180 top value=1uF
C93 "GRM21BR71C105KA01L" 0805_HV 7114.91,1528.75 r90 top value=1uF
C94 "06035A681FAT2A" 0603 7102.11,2137.8 r270 top value=680pF
C95 "CGA3E2X7R1H104K080AA" 0603 8065.95,2644.58 r0 bottom value=0.1uF
C96 "C1608X5R1E105K080AC" 0603 8065.95,2707.79 r0 bottom value=1uF
C97 "GRM21BR71C105KA01L" 0805_HV 7783.66,2758.11 r180 top value=1uF
C98 "06035A681FAT2A" 0603 7215.31,2586.81 r0 top value=680pF
C99 "CGA3E2X7R1H104K080AA" 0603L 7325.36,1139.35 r90 bottom value=0.1uF
C100 "C1608X5R1E105K080AC" 0603 7264.56,1139.16 r90 bottom value=1uF
C101 "GRM21BR71C105KA01L" 0805_HV 7109.32,1898.57 r270 top value=1uF
C102 "GRM21BR71C105KA01L" 0805_HV 6482.36,1842.9 r270 top value=1uF
C103 "06035A681FAT2A" 0603 7237.23,2137.8 r270 top value=680pF
C104 "CGA3E2X7R1H104K080AA" 0603 8029.91,3182.18 r0 bottom value=0.1uF
C105 "C1608X5R1E105K080AC" 0603 8029.91,3247.28 r0 bottom value=1uF
C106 "GRM21BR71C105KA01L" 0805_HV 7502.59,2846.85 r0 top value=1uF
C107 "CGA3E2X7R1H104K080AA" 0603 7650.35,2107.72 r270 top value=0.1uF
C108 "06035A681FAT2A" 0603 7134.17,2813.99 r90 top value=680pF
C109 "CGA3E2X7R1H104K080AA" 0603 7745.47,1245.43 r270 bottom value=0.1uF
C110 "C1608X5R1E105K080AC" 0603 7681.16,1245.24 r270 bottom value=1uF
C111 "06035A681FAT2A" 0603 7215.31,2368.79 r0 top value=680pF
C112 "C3216X5R1A686M160AC" 1206_190 8249.99,1389.57 r315 top value=68uF
C114 "C0603C104K5RACTU" 0603 6666.99,3442.06 r270 top value=0.1uF
C115 "C0603C102J5GACTU" 0603 6519.76,3863.71 r90 top value=1000pF
C116 "C0603C102J5GACTU" 0603 6246.53,3863.71 r90 top value=1000pF
C117 "C0603C102J5GACTU" 0603 6929.6,3863.71 r90 top value=1000pF
C118 "C0603C102J5GACTU" 0603 6656.37,3863.71 r90 top value=1000pF
C119 "C0603C102J5GACTU" 0603 6383.14,3863.71 r90 top value=1000pF
C120 "C0603C102J5GACTU" 0603 6792.98,3863.71 r90 top value=1000pF
C121 "C0603C102J5GACTU" 0603 7066.21,3863.71 r90 top value=1000pF
C122 "08055C104KAT2A" 0805_HV 6329.24,2629.04 r270 top value=0.1uF
C123 "08055C104KAT2A" 0805_HV 6329.12,2410.23 r90 top value=0.1uF
C124 "CGA6P3X7S1H106K250AB" 1210_280 5238.51,3869.28 r180 top value=10uF
C125 "CGA6P3X7S1H106K250AB" 1210_280 5419.32,3758.46 r270 top value=10uF
C126 "CGA6P3X7S1H106K250AB" 1210_280 5435.46,4181.06 r0 top value=10uF
C128 "GRM31CR71E106MA12L" 1206 5191.21,2576.2 r180 top value=10uF
C133 "C1608X5R1E105K080AC" 0603L 8231.69,2144.46 r0 bottom value=1uF
C134 "C1608X5R1E105K080AC" 0603L 6704.69,1001.53 r270 bottom value=1uF
C135 "C1608X5R1E105K080AC" 0603 8226.44,2713.35 r180 bottom value=1uF
C136 "C1608X5R1E105K080AC" 0603L 7261.64,1001.53 r270 bottom value=1uF
C137 "C1608X5R1E105K080AC" 0603 8219.25,3284.86 r180 bottom value=1uF
C138 "C1608X5R1E105K080AC" 0603 7835.13,1051.55 r90 bottom value=1uF
C139 "C1608X5R1E105K080AC" 0603 6461.78,1713.73 r0 top value=1uF
C140 "C1608X5R1E105K080AC" 0603 7131,1646.77 r180 top value=1uF
C141 "C1608X5R1E105K080AC" 0603 7131.32,1783.28 r180 top value=1uF
C142 "C1608X5R1E105K080AC" 0603 5637.48,1032.52 r90 bottom value=1uF
C143 "C1608X5R1E105K080AC" 0603 7317.17,1001.54 r90 bottom value=1uF
C144 "C1608X5R1E105K080AC" 0603 7642.08,2772.57 r270 top value=1uF
C145 "C1608X5R1E105K080AC" 0603L 6205.88,1010.25 r90 bottom value=1uF
C146 "C1608X5R1E105K080AC" 0603 7721.11,2108.06 r90 top value=1uF
C147 "C1608X5R1E105K080AC" 0603 7581.12,2108.16 r90 top value=1uF
C148 "C1608X5R1E105K080AC" 0603L 6758.07,1003.92 r90 bottom value=1uF
C149 "C1608X5R1E105K080AC" 0603 8244.76,1605.56 r180 bottom value=1uF
C150 "C1608X5R1E105K080AC" 0603 8242.67,2201.68 r180 bottom value=1uF
C151 "C1608X5R1E105K080AC" 0603L 6142.86,1009.64 r270 bottom value=1uF
C152 "06035A681FAT2A" 0603 7001.72,2813.99 r90 top value=680pF
C153 "CGA3E2X7R1H104K080AA" 0603 6142.52,1139.35 r90 bottom value=0.1uF
C154 "CGA3E2X7R1H104K080AA" 0603 7131,1713.73 r0 top value=0.1uF
C155 "C1608X5R1E105K080AC" 0603L 6205.76,1139.35 r90 bottom value=1uF
C156 "C0603C102J5GACTU" 0603 7202.92,3864.22 r90 top value=1000pF
C160 "C1608X5R1E105K080AC" 0603L 8236.28,2772.2 r180 bottom value=1uF
C164 "GCJ21AR72E102KXJ1D" FP-GCJ21AR72E102KXJ1D_0805-MFG 6583.4,3080.12 r180 bottom value=1nF
Charger "ED120/2DS" On-Shore_ED120_2DS 3759.84,2705.77 r270 top
Charger_ "575-8" Keystone575-8 3654.53,2180.81 r180 top
D1 "SM4003PL-TP" SOD-123FL 5824.02,3432.47 r270 top value=200V
D2 "SM4003PL-TP" SOD-123FL 5721.53,3432.47 r270 top value=200V
D3 "SM4003PL-TP" SOD-123FL 4677.06,2951.16 r180 top value=200V
D4 "MMSZ5234B-7-F" SOD-123 4194.1,2622.2 r180 top value=6.2V
D5 "MMSZ5234B-7-F" SOD-123 4194.1,2719.91 r180 top value=6.2V
D6 "MMSZ5234B-7-F" SOD-123 4239.24,1536.45 r180 bottom value=6.2V
D7 "SM4003PL-TP" SOD-123FL 5425.27,3924.4 r180 top value=200V
D8 "SM4003PL-TP" SOD-123FL 5446.5,4053.19 r0 top value=200V
D9 "SM4003PL-TP" SOD-123FL 5467.27,3384.11 r90 top value=200V
D10 "SM4003PL-TP" SOD-123FL 5229.31,3644.83 r180 top value=200V
FID1 "Fiducial" Fiducial10-20 3466.42,4284.74 r90 top
FID2 "Fiducial" Fiducial10-20 3455.46,421 r90 top
FID3 "Fiducial" Fiducial10-20 8854.74,4300.95 r90 top
GND "575-8" Keystone575-8 4863.79,618.56 r90 top
GND_ "575-8" Keystone575-8 3654.53,1691.34 r90 top
H1 "NY PMS 440 0025 PH" "NY PMS 440 0025 PH" 3649.62,4118.47 r0 top
H2 "NY PMS 440 0025 PH" "NY PMS 440 0025 PH" 3645.09,589.63 r0 top
H4 "NY PMS 440 0025 PH" "NY PMS 440 0025 PH" 8678.54,4129.28 r0 top
H5 "1902C" Keystone_1902C 3649.62,4118.47 r180 bottom
H6 "1902C" Keystone_1902C 3645.09,589.63 r180 bottom
H8 "1902C" Keystone_1902C 8678.54,4129.28 r180 bottom
I2C_pull "SL 11 112 02G" Fischer_SL-11-112-02G 7055.82,3121.98 r45 top
J1 "SL 11 112 03G" Fischer_SL-11-112-03G 7890.2,3657.49 r90 top
J2 "TSW-105-07-G-S" TSW-105-07-X-S 6577.98,2750.6 r270 top
J3 "S9B-XH-A (LF)(SN)" "FP-S9B-XH-A (LF)(SN)_CONN_FFC_9P-MFG" 8525.8,795.09 r45 bottom
J4 "SL 11 112 03G" Fischer_SL-11-112-03G 5935.04,3898.15 r90 top
J5 "SL 11 112 03G" Fischer_SL-11-112-03G 7479.65,1823.8 r180 top
J6 "SL 11 112 03G" Fischer_SL-11-112-03G 6827.93,3488.25 r90 top
J_1V85 "SL 11 112 02G" Fischer_SL-11-112-02G 6250.39,3116.66 r180 top
J_2V5 "SL 11 112 02G" Fischer_SL-11-112-02G 8290.56,1504.3 r315 top
J_3V3 "SL 11 112 02G" Fischer_SL-11-112-02G 5279.91,2828.58 r0 top
J_3V3_2 "SL 11 112 02G" Fischer_SL-11-112-02G 6758.79,3190.32 r270 top
J_5V "SL 11 112 02G" Fischer_SL-11-112-02G 6455.13,2011.11 r0 top
J_heater "SL 11 112 02G" Fischer_SL-11-112-02G 7131.21,4186.51 r180 top
J_LS "SL 11 112 02G" Fischer_SL-11-112-02G 5414.11,2044.18 r90 top
J_pump "SL 11 112 02G" Fischer_SL-11-112-02G 5179.78,4054.49 r180 top
J_PWM "SL 11 112 02G" Fischer_SL-11-112-02G 5596.01,3659.4 r180 top
JTAG "SBH11-PBPC-D07-ST-BK" CONN_SBH11-PBPC-D07-ST-BK 7870.58,4041.54 r180 top
LBL1 "THT-14-423-10" Label_650x200 4960.63,4236.17 r180 top
Load "ED120/2DS" On-Shore_ED120_2DS 3759.84,3233.6 r270 top
Load_ "575-8" Keystone575-8 4205.71,3514.5 r90 top
LOAD_GND "575-8" Keystone575-8 3654.53,3701.3 r90 top
Logo1 "CE Mark" CE_Mark_5mm 5848.26,1580.56 r0 top
Logo2 "Texas Instruments" TI_Symbol_Overlay_Small 8518.65,3866.34 r0 top
Logo3 "FCC disclaimer" FCC_disclaimer 7716.06,4299.03 r0 top
Logo4 "WEEE logo" WEEE_Minimum 6122.28,1615.72 r0 top
Q1 "ZXTP25040DFHTA" SOT-23 7631.56,853.42 r0 top value="40 V"
Q2 "ZXTP25040DFHTA" SOT-23 5918.23,863.99 r90 top value="40 V"
Q3 "PBSS8110T" SOT-23 7496.55,992.11 r180 top value="100 V"
Q4 "PBSS8110T" SOT-23 5782.26,1085.71 r180 top value="100 V"
Q5 "ZXTP25040DFHTA" SOT-23 8443.46,1892.25 r180 top value="40 V"
Q6 "PBSS8110T" SOT-23 8244.02,1753.54 r270 top value="100 V"
Q7 "ZXTP25040DFHTA" SOT-23 6463.44,867.35 r90 top value="40 V"
Q8 "PBSS8110T" SOT-23 6341.8,1098.85 r180 top value="100 V"
Q9 "ZXTP25040DFHTA" SOT-23 8434.28,2344.95 r180 top value="40 V"
Q10 "PBSS8110T" SOT-23 8229.57,2211.34 r270 top value="100 V"
Q11 "MMBT3904LP" DIODES_X1-DFN1006-3 7167.2,3968.92 r90 top value="40 V"
Q12 "ZXTP25040DFHTA" SOT-23 6988.19,863.99 r90 top value="40 V"
Q13 "PBSS8110T" SOT-23 6873.34,1087.69 r180 top value="100 V"
Q14 "ZXTP25040DFHTA" SOT-23 8442.28,2809.79 r180 top value="40 V"
Q15 "PBSS8110T" SOT-23 8244.02,2649.79 r270 top value="100 V"
Q17 "SQJQ466E-T1_GE3" "FP-SQJQ466E-T1_GE3_PowerPAK 8 x 8L-MFG" 4092.59,2308.6 r90 top
Q18 "SQJQ466E-T1_GE3" "FP-SQJQ466E-T1_GE3_PowerPAK 8 x 8L-MFG" 4445.27,2391.47 r270 top
Q19 "SQJQ466E-T1_GE3" "FP-SQJQ466E-T1_GE3_PowerPAK 8 x 8L-MFG" 4094.96,2318.22 r270 bottom
Q20 "SQJQ466E-T1_GE3" "FP-SQJQ466E-T1_GE3_PowerPAK 8 x 8L-MFG" 4445.27,2263.37 r90 bottom
Q21 "SQJQ466E-T1_GE3" "FP-SQJQ466E-T1_GE3_PowerPAK 8 x 8L-MFG" 4460.19,1791.21 r90 bottom
Q22 "SQJQ466E-T1_GE3" "FP-SQJQ466E-T1_GE3_PowerPAK 8 x 8L-MFG" 4139.72,4076.32 r90 top
Q23 "SQJQ466E-T1_GE3" "FP-SQJQ466E-T1_GE3_PowerPAK 8 x 8L-MFG" 4112.53,1813.56 r270 bottom
Q24 "2N7002KW" SOT-323 4806.43,2725.82 r0 top value=60V
Q25 "MMBT3904LP" DIODES_X1-DFN1006-3 6621.84,3968.92 r90 top value="40 V"
Q26 "MMBT3904LP" DIODES_X1-DFN1006-3 6485.5,3968.92 r90 top value="40 V"
Q27 "MMBT3904LP" DIODES_X1-DFN1006-3 6349.16,3968.92 r90 top value="40 V"
Q28 "MMBT3904LP" DIODES_X1-DFN1006-3 6212.82,3968.92 r90 top value="40 V"
Q29 "MMBT3904LP" DIODES_X1-DFN1006-3 6758.18,3968.92 r90 top value="40 V"
Q30 "MMBT3904LP" DIODES_X1-DFN1006-3 6894.52,3968.92 r90 top value="40 V"
Q31 "MMBT3904LP" DIODES_X1-DFN1006-3 7030.86,3968.92 r90 top value="40 V"
Q32 "PBSS8110T" SOT-23 5750.5,3810.22 r0 top value="100 V"
Q33 "MMBT2907ALT1G" SOT-23 5588.16,3810.22 r180 top value="60 V"
Q34 "PBSS8110T" SOT-23 5609.52,3987.61 r270 top value="100 V"
Q35 "MMBT2907ALT1G" SOT-23 4752.15,3300.4 r270 top value="60 V"
Q36 "SI2337DS-T1-E3" SOT-23 7950.19,1342.83 r45 top value=-80V
Q37 "2N7002KW" SOT-323 7634.28,1084.91 r0 top value=60V
Q38 "PBSS8110T" SOT-23 4920.66,3086.76 r90 top value="100 V"
Q39 "2N7002KW" SOT-323 4333.66,1631.84 r180 top value=60V
Q40 "2N7002KW" SOT-323 4981.28,2785.37 r270 top value=60V
Q41 "2N7002KW" SOT-323 8403.5,1273.15 r225 top value=60V
Q42 "SI2337DS-T1-E3" SOT-23 6595.91,3191.57 r0 bottom value=-80V
Q43 "2N7002KW" SOT-323 4247.69,1899.36 r270 top value=60V
Q44 "2N7002KW" SOT-323 4839.75,2839.61 r90 top value=60V
Q45 "2N7002KW" SOT-323 4752.15,3701.3 r180 top value=60V
Q46 "2N7002KW" SOT-323 4333.66,1750.58 r180 top value=60V
Q47 "2N7002KW" SOT-323 4700.34,3821.45 r270 top value=60V
Q48 "2N7002KW" SOT-323 4364.25,1899.36 r270 top value=60V
Q49 "PBSS8110T" SOT-23 8374.87,3531.79 r180 top value="100 V"
Q50 "2N7002KW" SOT-323 5928.36,2709.5 r90 top value=60V
R1 "ERJ-6GEYJ103V" 0805_HV 5732.23,4078.78 r90 top value=10k
R2 "RG2012P-103-B-T5" 0805_HV 6378.86,1842.9 r90 top value=10.0k
R3 "RC0603FR-0784R5L" 0603 6899.49,2137.8 r90 top value=84.5
R4 "RT0805BRD073K01L" 0805_HV 5833.52,1271.03 r90 bottom value=3.01k
R5 "RT0805BRD072K05L" 0805_HV 5930.29,1270.39 r90 bottom value=2.05k
R6 "RT0603BRD071KL" 0603 7134.38,3863.71 r270 top value=1.00k
R7 "CRCW0805499RFKEA" 0805_HV 7337.61,781.68 r90 top value=499
R8 "CRCW251224R9FKEGHP" FP-CRCW251224R9FKEGHP_2512-MFG 6062.35,922.99 r90 top value=24.9
R9 "CRCW0805499RFKEA" 0805_HV 5709.21,735.4 r90 top value=499
R10 "RG2012P-104-B-T5" 0805_HV 5486.97,1129.24 r180 top value=100k
R11 "RG2012P-2611-B-T5" 0805_HV 5636.62,3018.04 r0 top value=2.61k
R12 "RG2012P-102-B-T5" 0805_HV 4548.94,1213.6 r135 bottom value=1.00k
R13 "RT0805BRD0720KL" 0805_HV 6123.24,1959.82 r270 bottom value=20.0k
R14 "CRCW0805499RFKEA" 0805_HV 7681.17,972.94 r180 top value=499
R15 "RT0805BRD078K25L" 0805_HV 5486.73,1041.02 r0 top value=8.25k
R16 "RT0805BRD076K49L" 0805_HV 6101.04,2103.8 r0 bottom value=6.49k
R17 "RT0805BRD078K66L" 0805_HV 4710.38,1087.09 r180 bottom value=8.66k
R18 "RT0805BRD072K08L" 0805_HV 8091.68,1443.77 r225 top value=2.08k
R19 "RG2012P-472-B-T5" 0805_HV 5478.31,2758.19 r90 top value=4.70k
R20 "RG2012P-163-B-T5" 0805_HV 5171.55,2662.29 r0 top value=16.0k
R21 "CRCW08052K00JNEA" 0805_HV 6444.46,3134.49 r90 bottom value=2.0k
R22 "MCR10EZHJ000" 0805_HV 5253.78,3751.17 r180 top value=0
R23 "RT0805BRD079K31L" 0805_HV 5013.36,2513.54 r0 top value=9.31k
R24 "CRCW0805499RFKEA" 0805_HV 8562.42,1719.91 r180 top value=499
R25 "CRCW0805499RFKEA" 0805_HV 5973.68,1132.97 r180 top value=499
R26 "CRCW251224R9FKEGHP" FP-CRCW251224R9FKEGHP_2512-MFG 7819.44,757.73 r90 top value=24.9
R27 "CRCW251224R9FKEGHP" FP-CRCW251224R9FKEGHP_2512-MFG 6616.14,929.84 r90 top value=24.9
R28 "CRCW0805499RFKEA" 0805_HV 6270.76,733.87 r90 top value=499
R29 "CRCW0805499RFKEA" 0805_HV 8256.46,1893.8 r180 top value=499
R30 "CRCW0805499RFKEA" 0805_HV 8562.42,2173 r180 top value=499
R31 "CRCW0805499RFKEA" 0805_HV 6545.13,1128.31 r180 top value=499
R32 "CRCW251224R9FKEGHP" FP-CRCW251224R9FKEGHP_2512-MFG 8372.64,2036.46 r180 top value=24.9
R33 "CRCW251224R9FKEGHP" FP-CRCW251224R9FKEGHP_2512-MFG 7137.58,929.84 r90 top value=24.9
R34 "CRCW0805499RFKEA" 0805_HV 6775.32,757.93 r90 top value=499
R35 "CRCW0805499RFKEA" 0805_HV 8268.53,2353.53 r180 top value=499
R36 "CRCW0805499RFKEA" 0805_HV 8567.47,2641.19 r180 top value=499
R37 "CRCW251224R9FKEGHP" FP-CRCW251224R9FKEGHP_2512-MFG 8363.73,2487.53 r180 top value=24.9
R38 "CRCW0805499RFKEA" 0805_HV 7075.32,1134.94 r180 top value=499
R39 "CRCW0805499RFKEA" 0805_HV 8256.4,2773.17 r180 top value=499
R40 "CRCW251224R9FKEGHP" FP-CRCW251224R9FKEGHP_2512-MFG 8375.03,2949.31 r180 top value=24.9
R41 "CRCW080510K0FKEA" 0805_HV 4179.67,1744.68 r270 top value=10.0k
R42 "CRCW080510K0FKEA" 0805_HV 4729.26,2592.04 r270 top value=10.0k
R43 "CRCW251224R9FKEGHP" FP-CRCW251224R9FKEGHP_2512-MFG 8343.14,3386.03 r0 top value=24.9
R44 "3522ZR" 2512 4161.42,4104.33 r180 bottom value=0
R45 "CRCW080510K0FKEA" 0805_HV 4483.88,3833.3 r90 top value=10.0k
R46 "RT0805BRD0744K2L" 0805_HV 4621.99,1459.02 r0 top value=44.2k
R47 "CRCW080510K0FKEA" 0805_HV 4900.34,3301.83 r0 top value=10.0k
R48 "CRCW080510K0FKEA" 0805_HV 4900.97,3207.45 r180 top value=10.0k
R49 "RG2012P-104-B-T5" 0805_HV 4678.15,2845.27 r0 top value=100k
R50 "CRCW080510K0FKEA" 0805_HV 4880.75,2949.1 r0 top value=10.0k
R51 "CRCW080510K0FKEA" 0805_HV 4596.35,3134.01 r270 top value=10.0k
R52 "RG2012P-104-B-T5" 0805_HV 4478.99,1471.8 r270 top value=100k
R53 "CRCW080510K0FKEA" 0805_HV 4698.38,3134.01 r90 top value=10.0k
R54 "RT0805BRD0744K2L" 0805_HV 5152,3027.11 r0 top value=44.2k
R55 "RC1206FR-071ML" 1206 4779.71,2318.8 r180 top value=1.00Meg
R56 "RG2012P-104-B-T5" 0805_HV 4773.06,2081.02 r180 top value=100k
R57 "RT0805BRD076K04L" 0805_HV 4622.26,1558.68 r180 top value=6.04k
R58 "ERJ-8ENF6192V" 1206 4779.71,2435.48 r0 top value=61.9k
R59 "RT0805BRD076K04L" 0805_HV 5152,3143.62 r180 top value=6.04k
R60 "M55342K06B49D9T" 0805_HV 7366.67,936.36 r90 top value=49.9
R61 "M55342K06B49D9T" 0805_HV 5779.71,935.51 r90 top value=49.9
R63 "CRCW080510K0FKEA" 0805_HV 5920.67,2858.1 r90 top value=10.0k
R64 "M55342K06B49D9T" 0805_HV 8397.92,1719.46 r180 top value=49.9
R65 "M55342K06B49D9T" 0805_HV 6349.36,939.97 r90 top value=49.9
R66 "MCR10EZHJ000" 0805_HV 6178.68,734.28 r270 top value=0
R67 "MCR10EZHJ000" 0805_HV 8546.37,3666.84 r0 top value=0
R68 "M55342K06B49D9T" 0805_HV 8398.93,2184.68 r180 top value=49.9
R70 "M55342K06B49D9T" 0805_HV 6836.35,935.51 r90 top value=49.9
R72 "M55342K06B49D9T" 0805_HV 8401.8,2650.99 r180 top value=49.9
R75 "CRCW0805499RFKEA" 0805_HV 8174.59,3577.15 r180 top value=499
R82 "RG2012P-103-B-T5" 0805_HV 7459.18,2039.77 r180 top value=10.0k
R83 "RC0603FR-0784R5L" 0603 7215.31,2514.2 r180 top value=84.5
R84 "RG2012P-103-B-T5" 0805_HV 6387.74,1590.96 r270 top value=10.0k
R85 "RT0805BRD073K01L" 0805_HV 8011.84,1678.79 r180 bottom value=3.01k
R86 "RC0603FR-0784R5L" 0603 7034.61,2137.8 r90 top value=84.5
R87 "RT0805BRD073K01L" 0805_HV 6375.2,1270.39 r90 bottom value=3.01k
R88 "RT0805BRD072K05L" 0805_HV 6473.93,1270.39 r90 bottom value=2.05k
R89 "RT0805BRD073K01L" 0805_HV 8012.7,2271.2 r180 bottom value=3.01k
R90 "RG2012P-103-B-T5" 0805_HV 7841.59,2131.55 r0 top value=10.0k
R91 "RC0603FR-0784R5L" 0603 7215.31,2659.55 r180 top value=84.5
R92 "RT0805BRD072K05L" 0805_HV 8012.15,2362.05 r180 bottom value=2.05k
R93 "RG2012P-103-B-T5" 0805_HV 7213.11,1528.75 r270 top value=10.0k
R94 "RT0805BRD073K01L" 0805_HV 6848.2,1278.58 r90 bottom value=3.01k
R95 "RC0603FR-0784R5L" 0603 7169.74,2137.8 r90 top value=84.5
R96 "RT0805BRD072K05L" 0805_HV 6937.83,1278.43 r90 bottom value=2.05k
R97 "RT0805BRD073K01L" 0805_HV 8008.59,2816.14 r180 bottom value=3.01k
R98 "RG2012P-103-B-T5" 0805_HV 7784.55,2849.79 r0 top value=10.0k
R99 "RC0603FR-0784R5L" 0603 7200.33,2813.99 r270 top value=84.5
R100 "RT0805BRD072K05L" 0805_HV 8009.11,2900.57 r180 bottom value=2.05k
R101 "RT0805BRD073K01L" 0805_HV 7400.92,1279 r90 bottom value=3.01k
R102 "RG2012P-103-B-T5" 0805_HV 7192.33,1897.8 r90 top value=10.0k
R103 "RC0603FR-0784R5L" 0603 7215.31,2296.18 r180 top value=84.5
R104 "RT0805BRD072K05L" 0805_HV 7489.53,1279.92 r90 bottom value=2.05k
R105 "RG2012P-104-B-T5" 0805_HV 7502.59,2757.28 r180 top value=100k
R106 "RT0805BRD0730K1L" 0805_HV 8334.23,3407.51 r180 bottom value=30.1k
R107 "RC0603FR-0784R5L" 0603 7067.88,2813.99 r270 top value=84.5
R108 "RT0805BRD0768K1L" 0805_HV 8334.97,3510.51 r180 bottom value=68.1k
R109 "RT0805BRD072K05L" 0805_HV 8012.15,1771.22 r180 bottom value=2.05k
R110 "ERJ-6GEYJ512V" 0805_HV 6939.43,3403.11 r270 top value=5.1k
R111 "ERJ-6GEYJ512V" 0805_HV 7038.95,3403.11 r270 top value=5.1k
R112 "RT0603BRD071KL" 0603 6588,3863.71 r270 top value=1.00k
R113 "RT0603BRD071KL" 0603 6451.38,3863.71 r270 top value=1.00k
R114 "RT0603BRD071KL" 0603 6314.77,3863.71 r270 top value=1.00k
R115 "RT0603BRD071KL" 0603 6178.16,3863.71 r270 top value=1.00k
R116 "RT0603BRD071KL" 0603 6724.61,3863.71 r270 top value=1.00k
R117 "RT0603BRD071KL" 0603 6861.22,3863.71 r270 top value=1.00k
R118 "RT0603BRD071KL" 0603 6997.84,3863.71 r270 top value=1.00k
R119 "CRCW0805100RJNEA" 0805_HV 5586.93,3503.21 r270 top value=100
R120 "ERJ-6GEYJ103V" 0805_HV 5775.3,3944.49 r0 top value=10k
R124 "RG2012P-104-B-T5" 0805_HV 6122.28,2629.04 r270 top value=100k
R128 "MCT06030Z0000ZP500" 0603 6636.86,4074.34 r90 top value=0
R129 "MCT06030Z0000ZP500" 0603 6708.36,4074.34 r90 top value=0
R130 "MCT06030Z0000ZP500" 0603 6457.84,4074.34 r90 top value=0
R131 "MCT06030Z0000ZP500" 0603 6529.34,4074.34 r90 top value=0
R132 "MCT06030Z0000ZP500" 0603 6277.66,4074.34 r90 top value=0
R133 "MCT06030Z0000ZP500" 0603 6349.16,4074.34 r90 top value=0
R139 "RT0805DRE0720KL" 0805_HV 7837.83,1247.03 r315 top value=20.0k
R140 "RG2012P-104-B-T5" 0805_HV 6122.28,2410.23 r90 top value=100k
R141 "RG2012P-103-B-T5" 0805_HV 6225.76,2629.04 r90 top value=10.0k
R142 "RG2012P-103-B-T5" 0805_HV 6225.7,2410.23 r270 top value=10.0k
R143 "RG2012P-303-B-T5" 0805_HV 7737.31,1143.09 r90 top value=30.0k
Rshunt1 "WSL36371L000FEA" WSL3637_0.001 4069.99,2981.57 r90 bottom value=0.001
Rshunt2 "WSL36373L000FEA" WSL3637_0_002 4074.8,1192.86 r270 bottom value=0.003
Sensor1 "SL 11 112 02G" Fischer_SL-11-112-02G 6761.17,4206.2 r180 top
Sensor2 "SL 11 112 02G" Fischer_SL-11-112-02G 6488.17,4206.2 r180 top
Sensor3 "SL 11 112 02G" Fischer_SL-11-112-02G 6215.18,4206.2 r180 top
"Supply Sel" "SL 11 112 03G" Fischer_SL-11-112-03G 4920.66,1067.72 r270 top
TP1 "5000" Keystone5000 5180.02,854.85 r90 top
TP2 "5001" Keystone5001 5584.98,854.85 r90 top
TP3 "5001" Keystone5001 8018.7,3342.29 r0 top
TP4 "5001" Keystone5001 7049.52,4059.15 r0 top
TP5 "5001" Keystone5001 6329.12,2833.12 r0 top
TP6 "5001" Keystone5001 3487.9,2903.99 r90 top
TP7 "TP_SM_1MM" TP_SM_1MM 7373.04,2510.57 r90 top
TP8 "5001" Keystone5001 8734.09,3693.57 r0 top
TP9 "5001" Keystone5001 7813.79,1877.57 r0 top
TP10 "5001" Keystone5001 3495.3,904.06 r90 top
TP11 "5001" Keystone5001 3487.9,3447.02 r0 top
TP12 "TP_SM_1MM" TP_SM_1MM 6928.03,2003.81 r90 top
TP13 "TP_SM_1MM" TP_SM_1MM 7339.04,2700.2 r90 top
TP14 "TP_SM_1MM" TP_SM_1MM 7179.87,2006 r180 top
TP15 "TP_SM_1MM" TP_SM_1MM 7292.77,2885.23 r90 top
TP16 "5000" Keystone5000 5694.28,564.59 r90 top
TP17 "TP_SM_1MM" TP_SM_1MM 6822.43,2030.79 r90 top
TP18 "TP_SM_1MM" TP_SM_1MM 7069.35,2961.2 r90 top
TP19 "5116" Keystone_5116 4319.28,2039.11 r270 top
TP20 "5116" Keystone_5116 4617.24,3447.94 r90 top
TP21 "5116" Keystone_5116 4615.16,3663.46 r90 top
TP22 "5000" Keystone5000 3495.3,2467.98 r90 top
TP23 "5000" Keystone5000 3487.9,3028.32 r90 top
TP24 "5000" Keystone5000 3495.3,1371.62 r90 top
TP25 "TP_SM_1MM" TP_SM_1MM 6242.76,1763.11 r90 top
TP26 "TP_SM_1MM" TP_SM_1MM 7859.57,1753.33 r90 top
TP27 "TP_SM_1MM" TP_SM_1MM 6304.69,1416.66 r90 top
TP28 "TP_SM_1MM" TP_SM_1MM 7870.26,2227.19 r90 top
TP29 "TP_SM_1MM" TP_SM_1MM 7329.65,1511.2 r90 top
TP30 "TP_SM_1MM" TP_SM_1MM 7885.52,2629 r90 top
TP31 "5116" Keystone_5116 4971.28,2659.55 r270 top
TP32 "TP_SM_1MM" TP_SM_1MM 7319.07,1915.65 r90 top
TP33 "5000" Keystone5000 7259.47,564.59 r270 top
TP34 "5000" Keystone5000 6183.04,564.59 r270 top
TP35 "5000" Keystone5000 6728.6,564.59 r270 top
TP36 "5000" Keystone5000 8677.97,1615.58 r90 top
TP37 "5000" Keystone5000 8724.25,2141.33 r180 top
TP38 "5000" Keystone5000 8722.04,2662.72 r0 top
TP39 "5000" Keystone5000 8731.99,3215.43 r90 top
TP40 "TP_SM_1MM" TP_SM_1MM 7349.43,1738.61 r90 top
TP41 "5116" Keystone_5116 6223.17,875.97 r90 top
TP43 "5116" Keystone_5116 8374.01,3677.2 r90 top
TP45 "TP_SM_1MM" TP_SM_1MM 4459.69,3048.05 r90 top
TP46 "TP_SM_1MM" TP_SM_1MM 4370.31,1280.16 r90 top
U1 "MSP430FR59691IRGZR" RGZ0048B_NV 7441.11,3366.85 r180 top
U2 "ADC128S102WGRQV" NAC0016A_N 6905.9,2490.84 r90 top
U3 "TPS7H2211HKR/EM" HKR0016A_Custom_A 5435.77,1487.08 r90 top
U4 "TPS7A4501HKU/EM" HKU0010_CUSTOM_A 5905.73,1934.18 r0 top
U5 "LM117QML-SP" NDT0003A 4596.26,1186.85 r90 top
U6 "TPS7A4501HKU/EM" HKU0010_CUSTOM_A 5673.86,2489.56 r90 top
U7 "LM4050WG2.5-MPR" NAC0010A-IPC_C 8063.4,1139.03 r45 top
U8 "TLV1H103MDBVTSEP" DBV0006A-MFG 4644.63,2793.79 r90 bottom
U9 "INA901HKX/EM" HKX0008A_Custom_A 4450.74,3011.3 r270 bottom
U10 "TLV1H103MDBVTSEP" DBV0006A-MFG 4354.92,1465 r270 top
U11 "INA901HKX/EM" HKX0008A_Custom_A 4187.43,1181.7 r90 top
U12 "TLV1H103MDBVTSEP" DBV0006A-MFG 4779.71,2199.3 r180 top
U15 "LMP7704-SP" 0-IPC_C 7642.08,2437.95 r90 top
U16 "INA1H94HKX/EM" HKX0008A-IPC_C 8235.57,1893.45 r90 bottom
U17 "INA1H94HKX/EM" HKX0008A-IPC_C 6453.08,1044.19 r0 bottom
U18 "INA1H94HKX/EM" HKX0008A-IPC_C 8235.57,2456.02 r90 bottom
U19 "LMP7704-SP" 0-IPC_C 6805.25,1715.26 r180 top
U20 "INA1H94HKX/EM" HKX0008A-IPC_C 7013.22,1044.19 r0 bottom
U21 "INA1H94HKX/EM" HKX0008A-IPC_C 8233.53,3017.89 r90 bottom
U22 "INA1H94HKX/EM" HKX0008A-IPC_C 7573.35,1044.19 r0 bottom
U23 "5962R2021401VXC" HKT0016A-IPC_C 6365.48,3440.3 r0 top
U25 "INA1H94HKX/EM" HKX0008A-IPC_C 5892.94,1044.19 r0 bottom
U26 "TPS7A4501HKU/EM" HKU0010_CUSTOM_A 5129.91,2171.57 r90 top
Y1 "ECS-.327-9-34QCS-TR" FP-ECS-.327-9-34QCS-TR_SMT_CRYSTAL_3MM2_1MM5-MFG 7443.95,3107.19 r180 bottom

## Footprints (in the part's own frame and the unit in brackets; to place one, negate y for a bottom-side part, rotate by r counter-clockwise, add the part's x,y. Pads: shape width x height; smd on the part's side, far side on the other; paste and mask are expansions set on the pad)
0-IPC_C [mil]
  rrect19% 80.92x20.66 smd paste+0 mask+0: 1(-200.54,150)
  rrect100% 80.92x20.66 smd paste+0 mask+0: 2(-200.54,100) 3(-200.54,50) 4(-200.54,0) 5(-200.54,-50) 6(-200.54,-100) 7(-200.54,-150) 8(200.54,-150) 9(200.54,-100) 10(200.54,-50) 11(200.54,0) 12(200.54,50) 13(200.54,100) 14(200.54,150)
  silkscreen extent -269,-192 140,192, body extent -245,-195 245,195, height 10
0603 [mm] "0603 from SM-752 data"
  rect 1x0.95 smd: 1(-0.8,0) 2(0.8,0)
  silkscreen extent -1.52,-0.69 1.52,0.69, body extent -0.87,-0.47 0.87,0.47, height 1
0603L [mm] "0603 from SM-752 data"
  rect 0.8x0.85 smd: 1(-0.7,0) 2(0.7,0)
  silkscreen extent -0.07,-0.33 0.07,0.33, body extent -0.87,-0.47 0.87,0.47, height 1
0805_HV [mil] "0805 with 30mil clearance between pads"
  rect 50x63 smd: 1(-40,0) 2(40,0)
  silkscreen extent -74,-40 74,40, body extent -43,-29 43,29, height 57
1206 [mm] "1206 from SM-752 data"
  rect 1.3x1.85 smd: 1(-1.45,0) 2(1.45,0)
  silkscreen extent -2.4,-1.21 2.4,1.21, body extent -1.7,-0.9 1.7,0.9, height 1.35
1206_190 [mm] "1206_190"
  rect 1.1x1.6 smd: 1(-1.7,0) 2(1.7,0)
  silkscreen extent -0.9,-1 0.9,1, body extent -1.75,-0.95 1.75,0.95, height 1.9
1210_220 [mm] "1210"
  rect 1.3x2.7 smd: 1(-1.45,0) 2(1.45,0)
  silkscreen extent -2.32,-1.57 2.32,1.57, body extent -1.7,-1.35 1.7,1.35, height 2.2
1210_280 [mm] "SMD, 2-Leads, Body 3.6x2.8mm, Height 2.8mm"
  rect 1.1x2.2 smd: 1(-1.65,0) 2(1.65,0)
  silkscreen extent -0.84,-1.4 0.84,1.4, body extent -1.8,-1.4 1.8,1.4, height 2.8
2512 [mm] "Chip Resistor, Body 6.3x3.2mm, IPC Medium Density"
  rect 1.3x3.4 smd: 1(-2.95,0) 2(2.95,0)
  silkscreen extent -1.9,-1.6 1.9,1.6, body extent -3.22,-1.67 3.22,1.67, height 0.71
6032-28 [mm] "Medium Density IPC based on Vishay Sprague 293D datasheet."
  rect 2.55x2.3 smd: 1(-2.375,0) 2(2.375,0)
  silkscreen extent -3.96,-1.75 3.2,1.82, body extent -3.15,-1.75 3.15,1.75, height 2.8
CAPC3225X270X30LL30 [mm] "Chip Capacitor, 2-Leads, Body 3.5x2.7mm, IPC High Density"
  rect 0.75x2.6 smd: 1(-1.525,0) 2(1.525,0)
  silkscreen extent -0.75,-1.2 0.75,1.2, body extent -1.75,-1.35 1.75,1.35, height 2.7
CE_Mark_5mm [mil] "Minimum text height for CE Mark"
  silkscreen extent -138,-98 138,98
CONN_SBH11-PBPC-D07-ST-BK [mm] "Sullins recommended land pattern"
  rect 1.65x1.65 hole 1.016 mask+0: 1(-7.62,-1.27)
  round 1.65 hole 1.016 mask+0: 2(-7.62,1.27) 3(-5.08,-1.27) 4(-5.08,1.27) 5(-2.54,-1.27) 6(-2.54,1.27) 7(0,-1.27) 8(0,1.27) 9(2.54,-1.27) 10(2.54,1.27) 11(5.08,-1.27) 12(5.08,1.27) 13(7.62,-1.27) 14(7.62,1.27)
  silkscreen extent -12.64,-5.08 12.64,4.7, body extent -12.64,-4.4 12.64,4.7, height 9.12
DBV0006A-MFG [mm]
  rrect17% 1.1x0.6 smd paste+0 mask+0: 1(-1.3,0.95) 2(-1.3,0) 3(-1.3,-0.95) 4(1.3,-0.95) 5(1.3,0) 6(1.3,0.95)
  silkscreen extent -2.52,-1.53 0.35,1.53, body extent -1.4,-1.45 1.4,1.45, height 1.45
DIODES_X1-DFN1006-3 [mm] "Diodes Recommended"
  rect 0.4x0.25 smd: 1(-0.35,0.225) 2(-0.35,-0.225)
  rect 0.4x0.7 smd: 3(0.35,0)
  silkscreen extent -0.87,-0.38 -0.69,0.38, body extent -0.54,-0.34 0.54,0.34, height 0.53
FCC_disclaimer [mil]
Fiducial10-20 [mm]
  round 1 smd mask+0.5: 1(0,0)
  Top Layer keep-out circle w1.178: c0,0 r0.5
Fischer_SL-11-112-02G [mm] "TH, 2-Leads, Body 2.5x5.08mm, Pitch 2.54mm"
  round 1.4 hole 0.9: 1(-1.27,0) 2(1.27,0)
  silkscreen extent -3.31,-1.25 2.54,1.25, body extent -2.54,-1.25 2.54,1.25, height 8.4
Fischer_SL-11-112-03G [mm] "TH, 3-Leads, Body 2.5x7.62mm, Pitch 2.54mm"
  rect 1.4x1.4 hole 0.9: 1(-2.54,0)
  round 1.4 hole 0.9: 2(0,0) 3(2.54,0)
  silkscreen extent -4.58,-1.25 3.81,1.25, body extent -3.81,-1.25 3.81,1.25, height 8.4
FP-06035C104J4Z2A_0603-MFG [mm]
  rrect13% 0.8x0.75 smd paste+0 mask+0: 1(-0.75,0) 2(0.75,0)
  silkscreen extent -0.87,-0.77 0.87,0.77, body extent -1.25,-0.58 1.25,0.58, height 0.25
FP-CRCW251224R9FKEGHP_2512-MFG [mm]
  rrect8% 1.25x3.35 smd paste+0 mask+0: 1(-3.125,0) 2(3.125,0)
  silkscreen extent -2.12,-1.65 2.12,1.65, body extent -3.85,-1.78 3.85,1.78, height 0.25
FP-ECS-.327-9-34QCS-TR_SMT_CRYSTAL_3MM2_1MM5-MFG [mm]
  rrect9% 1.1x1.9 smd paste+0 mask+0: 1(-1.25,0) 2(1.25,0)
  silkscreen extent -0.33,-0.8 0.33,0.8, body extent -1.6,-0.75 1.6,0.75, height 0.9
FP-GCJ21AR72E102KXJ1D_0805-MFG [mm]
  rrect15% 0.65x0.95 smd paste+0 mask+0: 1(-0.875,0) 2(0.875,0)
  silkscreen extent -0.18,-0.72 0.18,0.72, body extent -1,-0.63 1,0.63, height 1
FP-GMC31X7R106K50NT_1206-MFG [mil]
  rrect10% 40x65 smd paste+0 mask+0: 1(-60,0) 2(60,0)
  silkscreen extent -25,-35 25,35, body extent -84,-39 84,39, height 10
"FP-S9B-XH-A (LF)(SN)_CONN_FFC_9P-MFG" [mm]
  rrect7% 1.4x1.4 hole 0.9 paste-1000 mask+0: 1(10,-3.45)
  round 1.4 hole 0.9 paste-1000 mask+0: 2(7.5,-3.45) 3(5,-3.45) 4(2.5,-3.45) 5(0,-3.45) 6(-2.5,-3.45) 7(-5,-3.45) 8(-7.5,-3.45) 9(-10,-3.45)
  silkscreen extent -12.45,-5.75 13.05,5.75, body extent -12.45,-5.75 12.45,5.75, height 6.15
"FP-SQJQ466E-T1_GE3_PowerPAK 8 x 8L-MFG" [mm]
  rrect12% 1.15x0.82 smd paste+0 mask+0: 1(-3.045,-3.64) 2(-1.015,-3.64) 3(1.015,-3.64) 4(3.045,-3.64)
  round 4.13 smd paste+0 mask+0: 5(1.09,1.755)
  Top Layer region: -4,4.05 4,4.05 4,3.55 3.45,3.55 3.45,-0.44 4.125,-0.44 4.125,-1.29 3.055,-1.29 3.055,-0.54 -3.055,-0.54 -3.055,-1.29 -4.125,-1.29 -4.125,-0.44 -3.45,-0.44 -3.45,3.55 -4,3.55 -4,4.05
  silkscreen extent -4,-4.76 4,-1.67, body extent -4.23,-4.15 4.23,4.15, height 0.25
FP-T521D157M020ATE050_2917-MFG [mm]
  rrect5% 1.99x2.33 smd paste+0 mask+0: 1(3.01,0) 2(-3.01,0)
  silkscreen extent -4.9,-2.3 3.8,2.3, body extent -3.65,-2.15 3.65,2.15, height 3.1
HKR0016A_Custom_A [mil] "16-Leads, Body 11.3x9.9mm, Pitch 1.27mm, Thermal Pad 9x6.78mm"
  rrect25% 56x22 smd: 1(-263.5,175) 2(-263.5,125) 3(-263.5,75) 4(-263.5,25) 5(-263.5,-25) 6(-263.5,-75) 7(-263.5,-125) 8(-263.5,-175) 9(263.5,-175) 10(263.5,-125) 11(263.5,-75) 12(263.5,-25) 13(263.5,25) 14(263.5,75) 15(263.5,125) 16(263.5,175)
  rect 259.45x346.46 smd: 17(0,0)
  silkscreen extent -273,-222 194,221, body extent -290,-222 290,222, height 92
HKT0016A-IPC_C [mm]
  rrect100% 2x0.6 smd paste+0 mask+0: 1(-4.925,4.445) 2(-4.925,3.175) 3(-4.925,1.905) 4(-4.925,0.635) 5(-4.925,-0.635) 6(-4.925,-1.905) 7(-4.925,-3.175) 8(-4.925,-4.445) 9(4.925,-4.445) 10(4.925,-3.175) 11(4.925,-1.905) 12(4.925,-0.635) 13(4.925,0.635) 14(4.925,1.905) 15(4.925,3.175) 16(4.925,4.445)
  silkscreen extent -6.62,-5.21 3.72,5.21, body extent -6.02,-5.35 6.02,5.35, height 0.25
HKU0010_CUSTOM_A [mm] "HKU custom footprint"
  rrect18% 1.42x0.55 smd: 1(-5.84,2.54) 2(-5.84,1.27) 3(-5.84,0) 4(-5.84,-1.27) 5(-5.84,-2.54) 6(5.84,-2.54) 7(5.84,-1.27) 8(5.84,0) 9(5.84,1.27) 10(5.84,2.54)
  rrect11% 0.95x0.95 on Top Paste: 11(-1.725,-2.875) 11(-1.725,-1.725) 11(-1.725,-0.575) 11(-1.725,0.575) 11(-1.725,1.725) 11(-1.725,2.875) 11(-0.575,-2.875) 11(-0.575,-1.725) 11(-0.575,-0.575) 11(-0.575,0.575) 11(-0.575,1.725) 11(-0.575,2.875) 11(0.575,-2.875) 11(0.575,-1.725) 11(0.575,-0.575) 11(0.575,0.575) 11(0.575,1.725) 11(0.575,2.875) 11(1.725,-2.875) 11(1.725,-1.725) 11(1.725,-0.575) 11(1.725,0.575) 11(1.725,1.725) 11(1.725,2.875)
  rrect4% 4.5x6.82 smd paste-3 mask-0.05: 11(0,0)
  silkscreen extent -3.56,-3.68 3.56,3.68, body extent -5.84,-3.6 5.84,3.6, height 2.59
HKX0008A-IPC_C [mm]
  rrect100% 2x0.65 smd paste+0 mask+0: 1(-4.575,1.905) 2(-4.575,0.635) 3(-4.575,-0.635) 4(-4.575,-1.905) 5(4.575,-1.905) 6(4.575,-0.635) 7(4.575,0.635) 8(4.575,1.905)
  silkscreen extent -6.29,-3.36 3.37,3.36, body extent -5.43,-3.24 5.43,3.24, height 2.79
HKX0008A_Custom_A [mm] "CFP, 8-Leads, Body 6.475x6.485mm, Pitch 1.27mm"
  rrect17% 2.5x0.6 smd: 1(-4.7,1.905) 2(-4.7,0.635) 3(-4.7,-0.635) 4(-4.7,-1.905) 5(4.7,-1.905) 6(4.7,-0.635) 7(4.7,0.635) 8(4.7,1.905)
  silkscreen extent -5.5,-3.36 3.37,3.36, body extent -3.25,-3.24 3.25,3.24, height 2.51
Keystone575-8 [mm] "Banana Jack"
  round 10 hole 5.45: 1(0,0)
  silkscreen extent -5.23,-5.23 5.23,5.23, body extent -3.92,-3.94 3.95,3.94, height 2.36
Keystone5000 [mil] "For Keystone 500x miniature loop terminals"
  round 80 hole 40: 1(0,0)
  silkscreen extent -52,-52 52,52, body extent -49,-49 49,49, height 182
Keystone5001 [mil] "For Keystone 500x miniature loop terminals"
  round 80 hole 40: 1(0,0)
  silkscreen extent -52,-52 52,52, body extent -49,-49 49,49, height 182
Keystone_1902C [mil] "Hex Standoff, 4-40 threaded, nylon"
  round 1 on Mech4: 0(0,0)
  body extent -145,-126 146,126, height 501
Keystone_5116 [mil] "For Keystone 500x miniature loop terminals"
  round 80 hole 40: 1(0,0)
  silkscreen extent -58,-58 58,58, body extent -50,-49 50,51, height 183
Label_650x200 [mil] "Thermal Transfer Label"
  round 1 on Mech13: 0(0,0)
  silkscreen extent -325,-100 325,100, body extent -325,-100 325,100, height 1
NAC0010A-IPC_C [mm]
  rrect16% 1.79x0.63 smd paste+0 mask+0: 1(-4.74,2.54) 2(-4.74,1.27) 3(-4.74,0) 4(-4.74,-1.27) 5(-4.74,-2.54) 6(4.74,-2.54) 7(4.74,-1.27) 8(4.74,0) 9(4.74,1.27) 10(4.74,2.54)
  silkscreen extent -6.48,-3.43 3.31,3.43, body extent -5.73,-3.53 5.73,3.53, height 0.25
NAC0016A_N [mm] "CFP, 16-Leads, Body 9.91x6.85mm, Pitch 1.27mm, IPC Medium Density"
  rrect17% 2.1x0.6 smd: 1(-4.7,4.445) 2(-4.7,3.175) 3(-4.7,1.905) 4(-4.7,0.635) 5(-4.7,-0.635) 6(-4.7,-1.905) 7(-4.7,-3.175) 8(-4.7,-4.445) 9(4.7,-4.445) 10(4.7,-3.175) 11(4.7,-1.905) 12(4.7,-0.635) 13(4.7,0.635) 14(4.7,1.905) 15(4.7,3.175) 16(4.7,4.445)
  silkscreen extent -5.25,-4.97 3,4.97, body extent -5.22,-4.95 5.22,4.95, height 1.98
NDT0003A [mm] "Can; 3 Leads; Pin Circle Dia. 5.08 mm; Lead Dia. 0.48 mm (max)"
  rect 1.4x1.4 hole 0.8: 1(-2.54,0)
  round 1.4 hole 0.8: 2(0,-2.54) 3(2.54,0)
  silkscreen extent -5.47,-4.69 4.69,4.69, body extent -4.69,-4.69 4.69,4.69, height 4.7
"NY PMS 440 0025 PH" [mm] "4-40 nylon screw and mounting hole"
  round 8 hole 3.2: 1(0,0)
  body extent -3.3,-3.3 3.3,3.3, height 2.69
On-Shore_ED120_2DS [mm] "ONSHORE"
  rrect5% 2x2 hole 1.25: 1(-2.54,0)
  round 2 hole 1.25: 2(2.54,0)
  silkscreen extent -5.6,-4 5.12,5, body extent -5.78,-4 5.08,5, height 13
